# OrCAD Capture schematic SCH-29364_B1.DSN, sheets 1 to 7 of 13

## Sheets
1 A-02 PWR TREE: title: MCIMX6ULL-CM; rev: B1; company: Freescale Semiconductor; note: SCH-29364 PDF: SPF-29364; note: 6501 William Cannon Drive West; note: Austin, TX 78735-8598
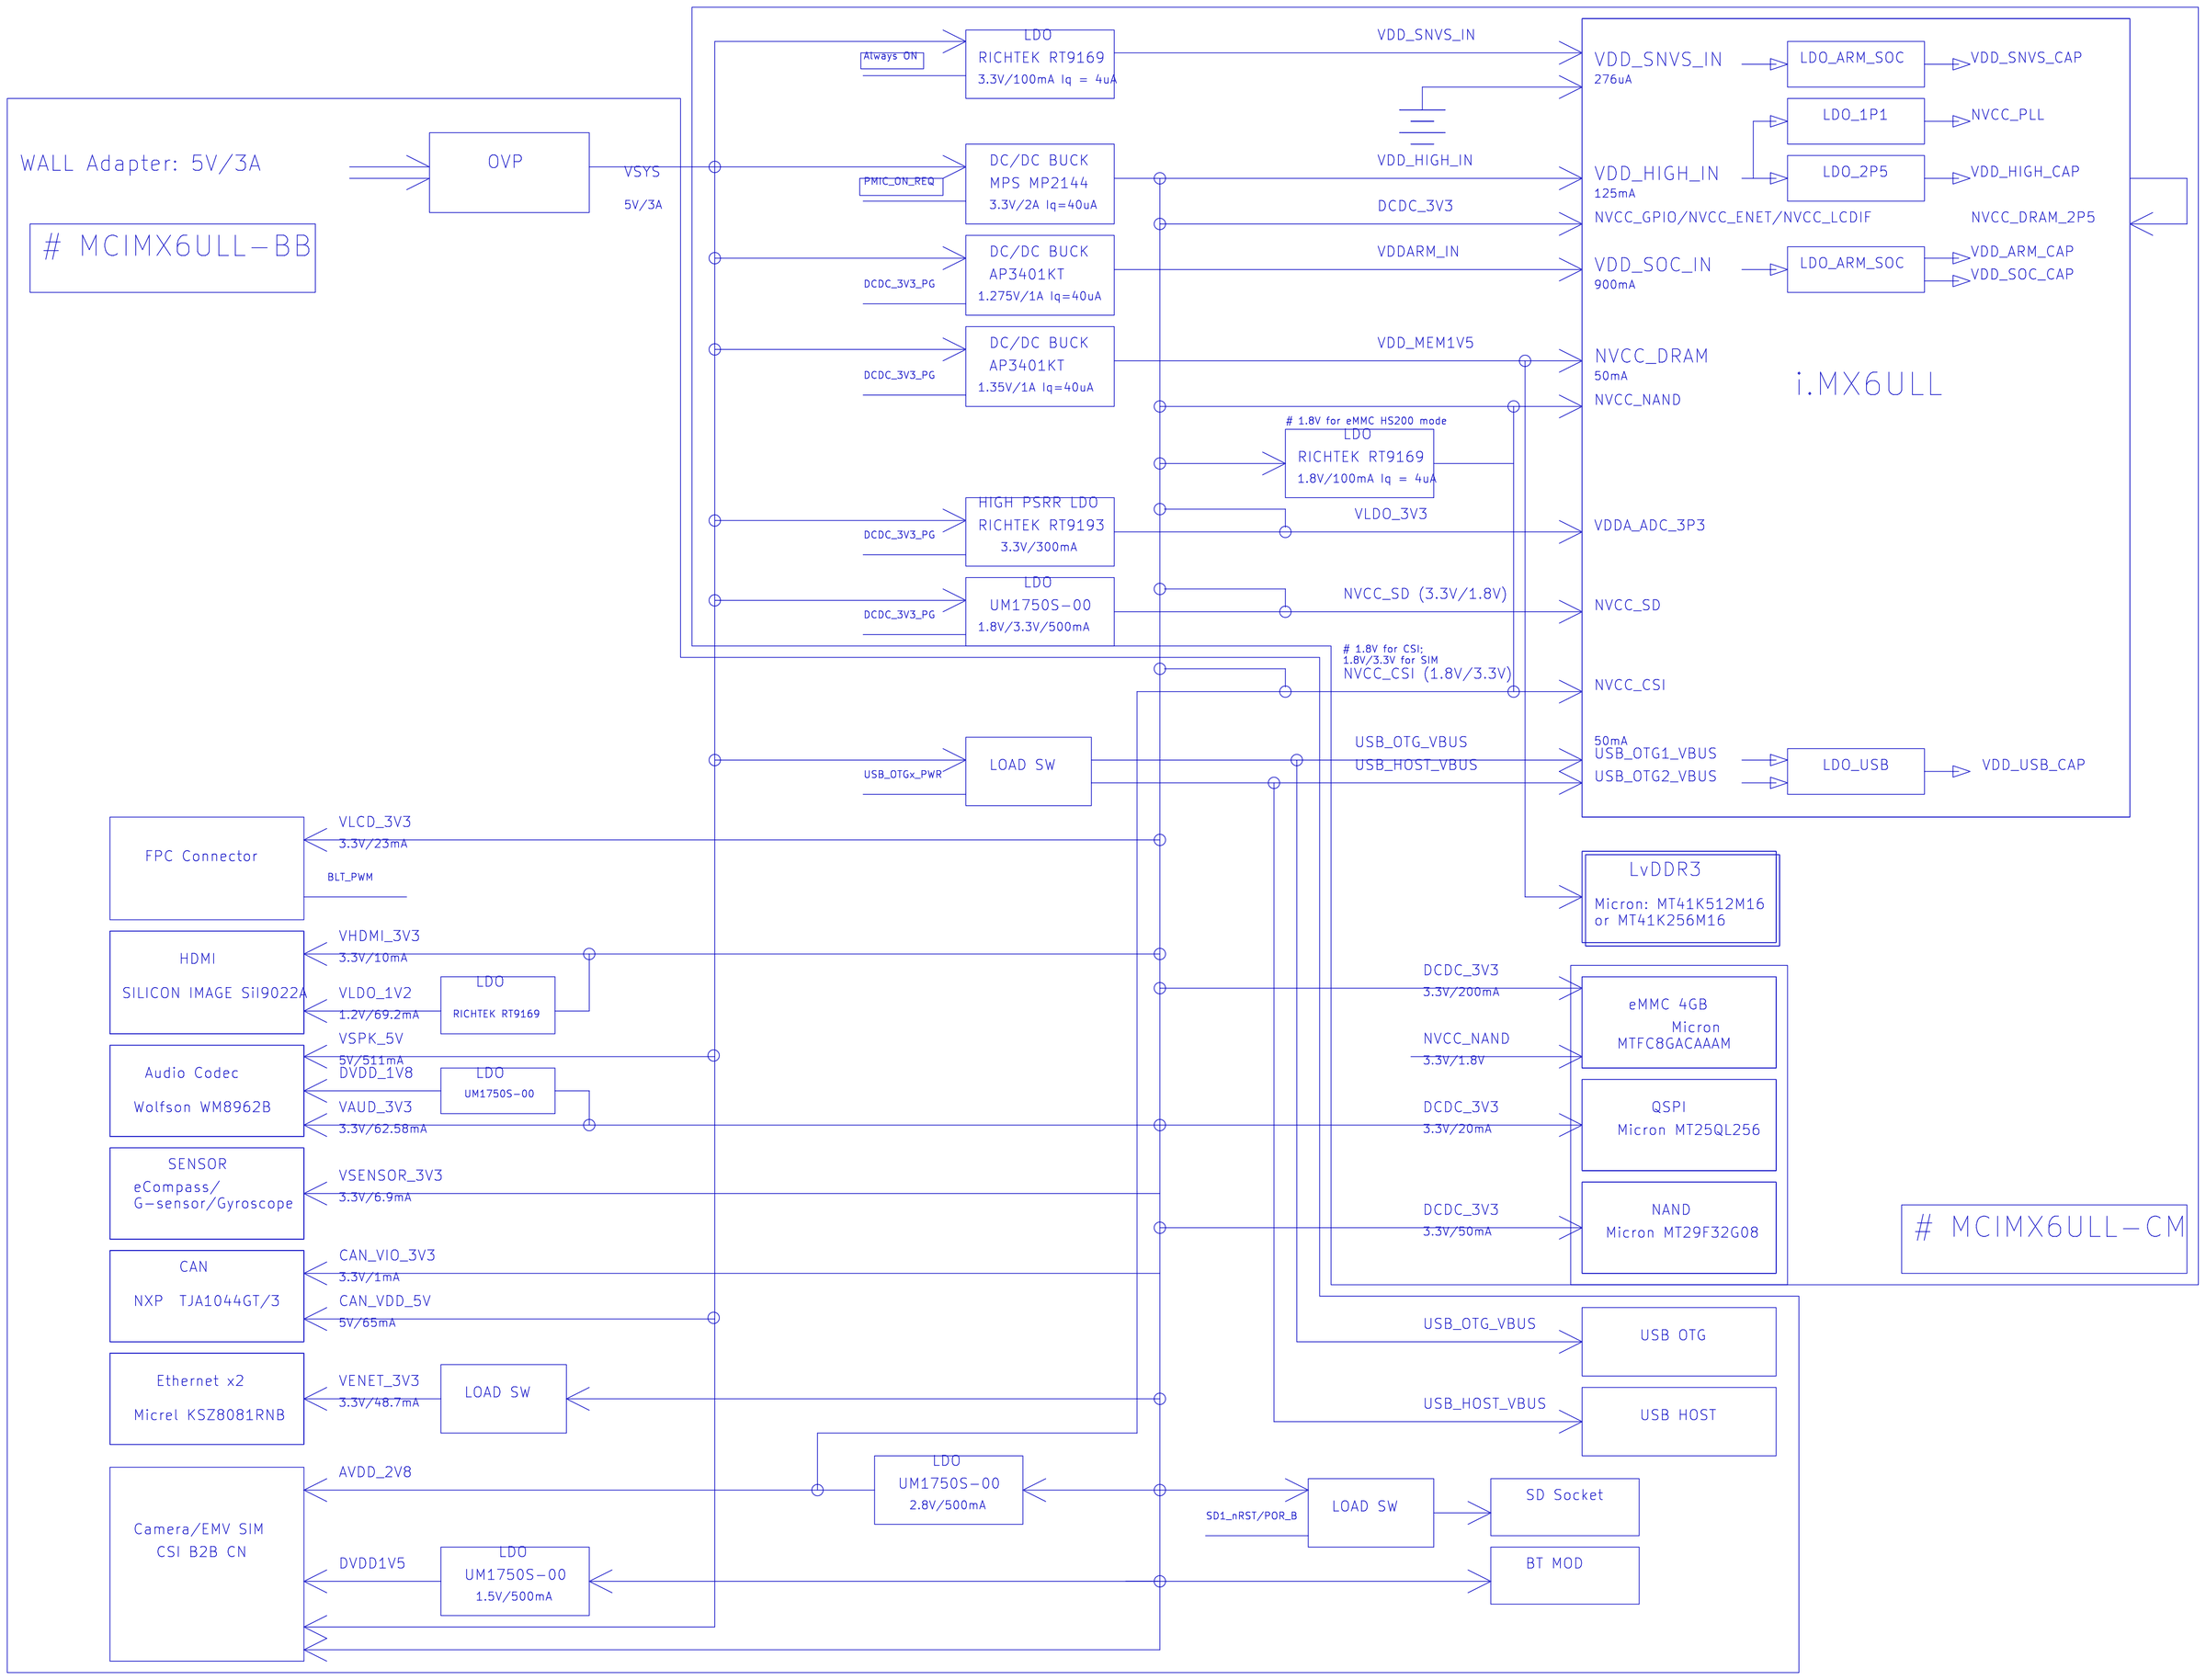
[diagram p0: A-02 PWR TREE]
2 A-01 BLOCK DIAGRAM
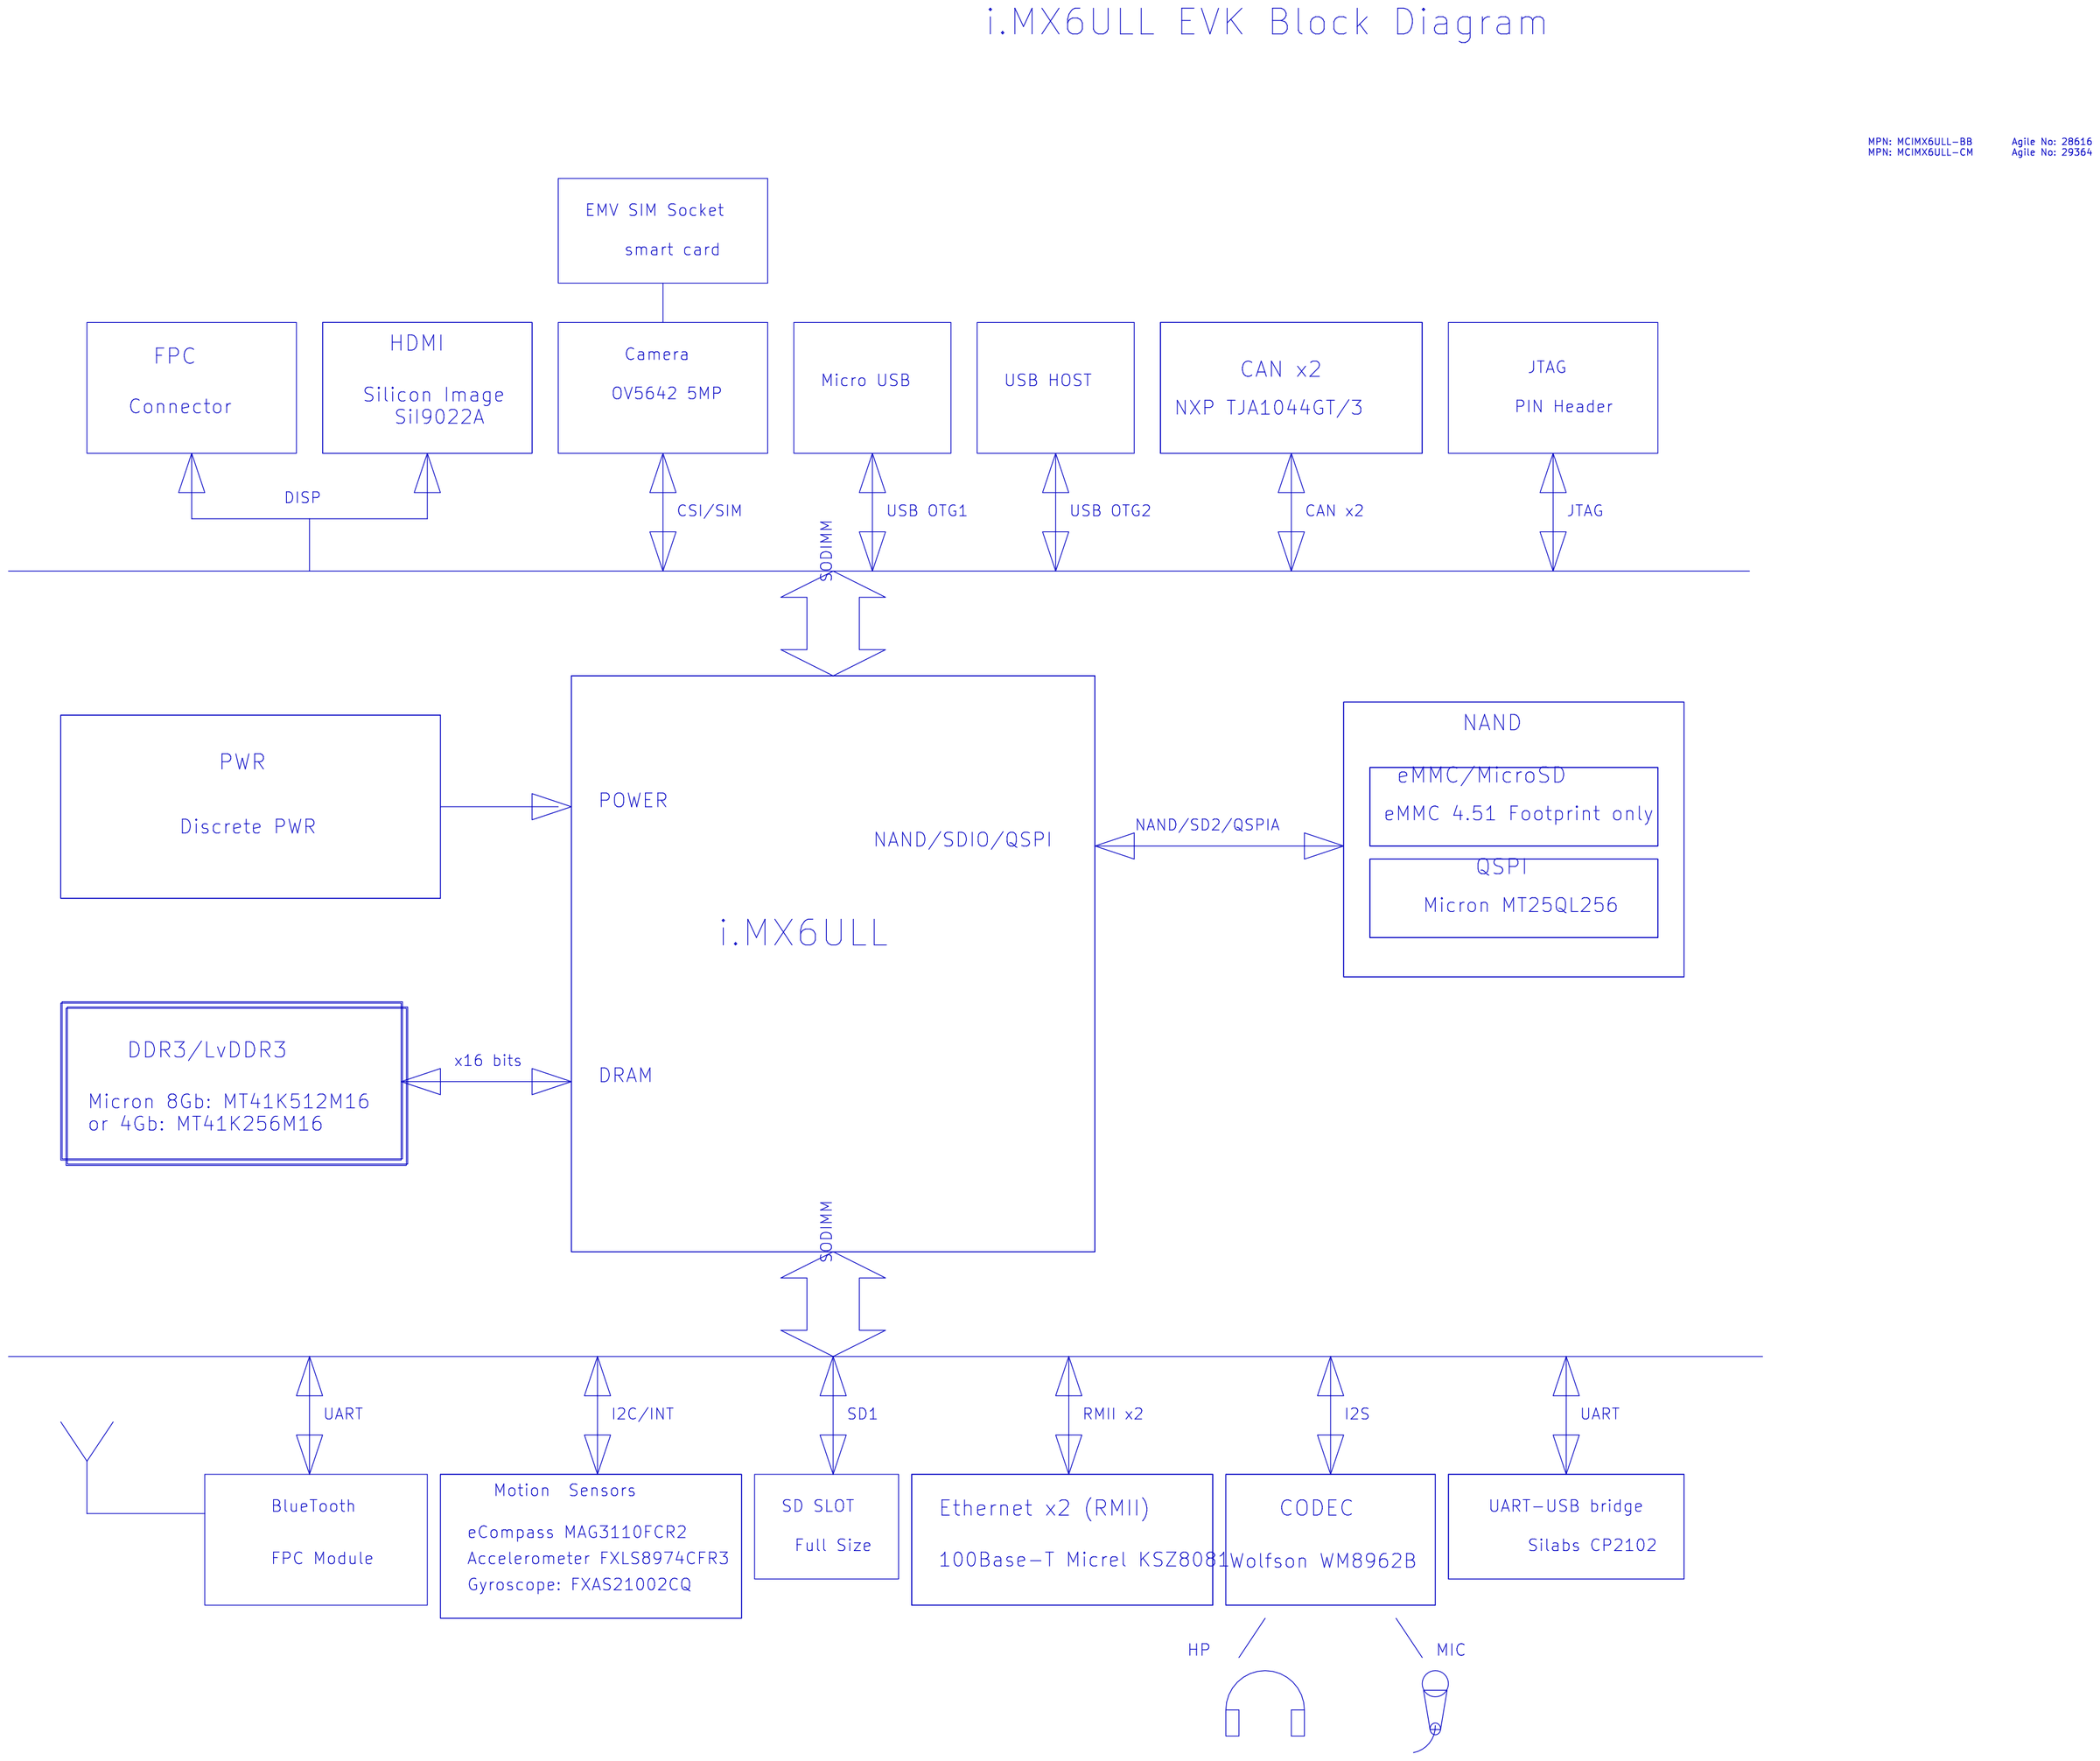
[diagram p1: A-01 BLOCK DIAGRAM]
3 A-00 COVER
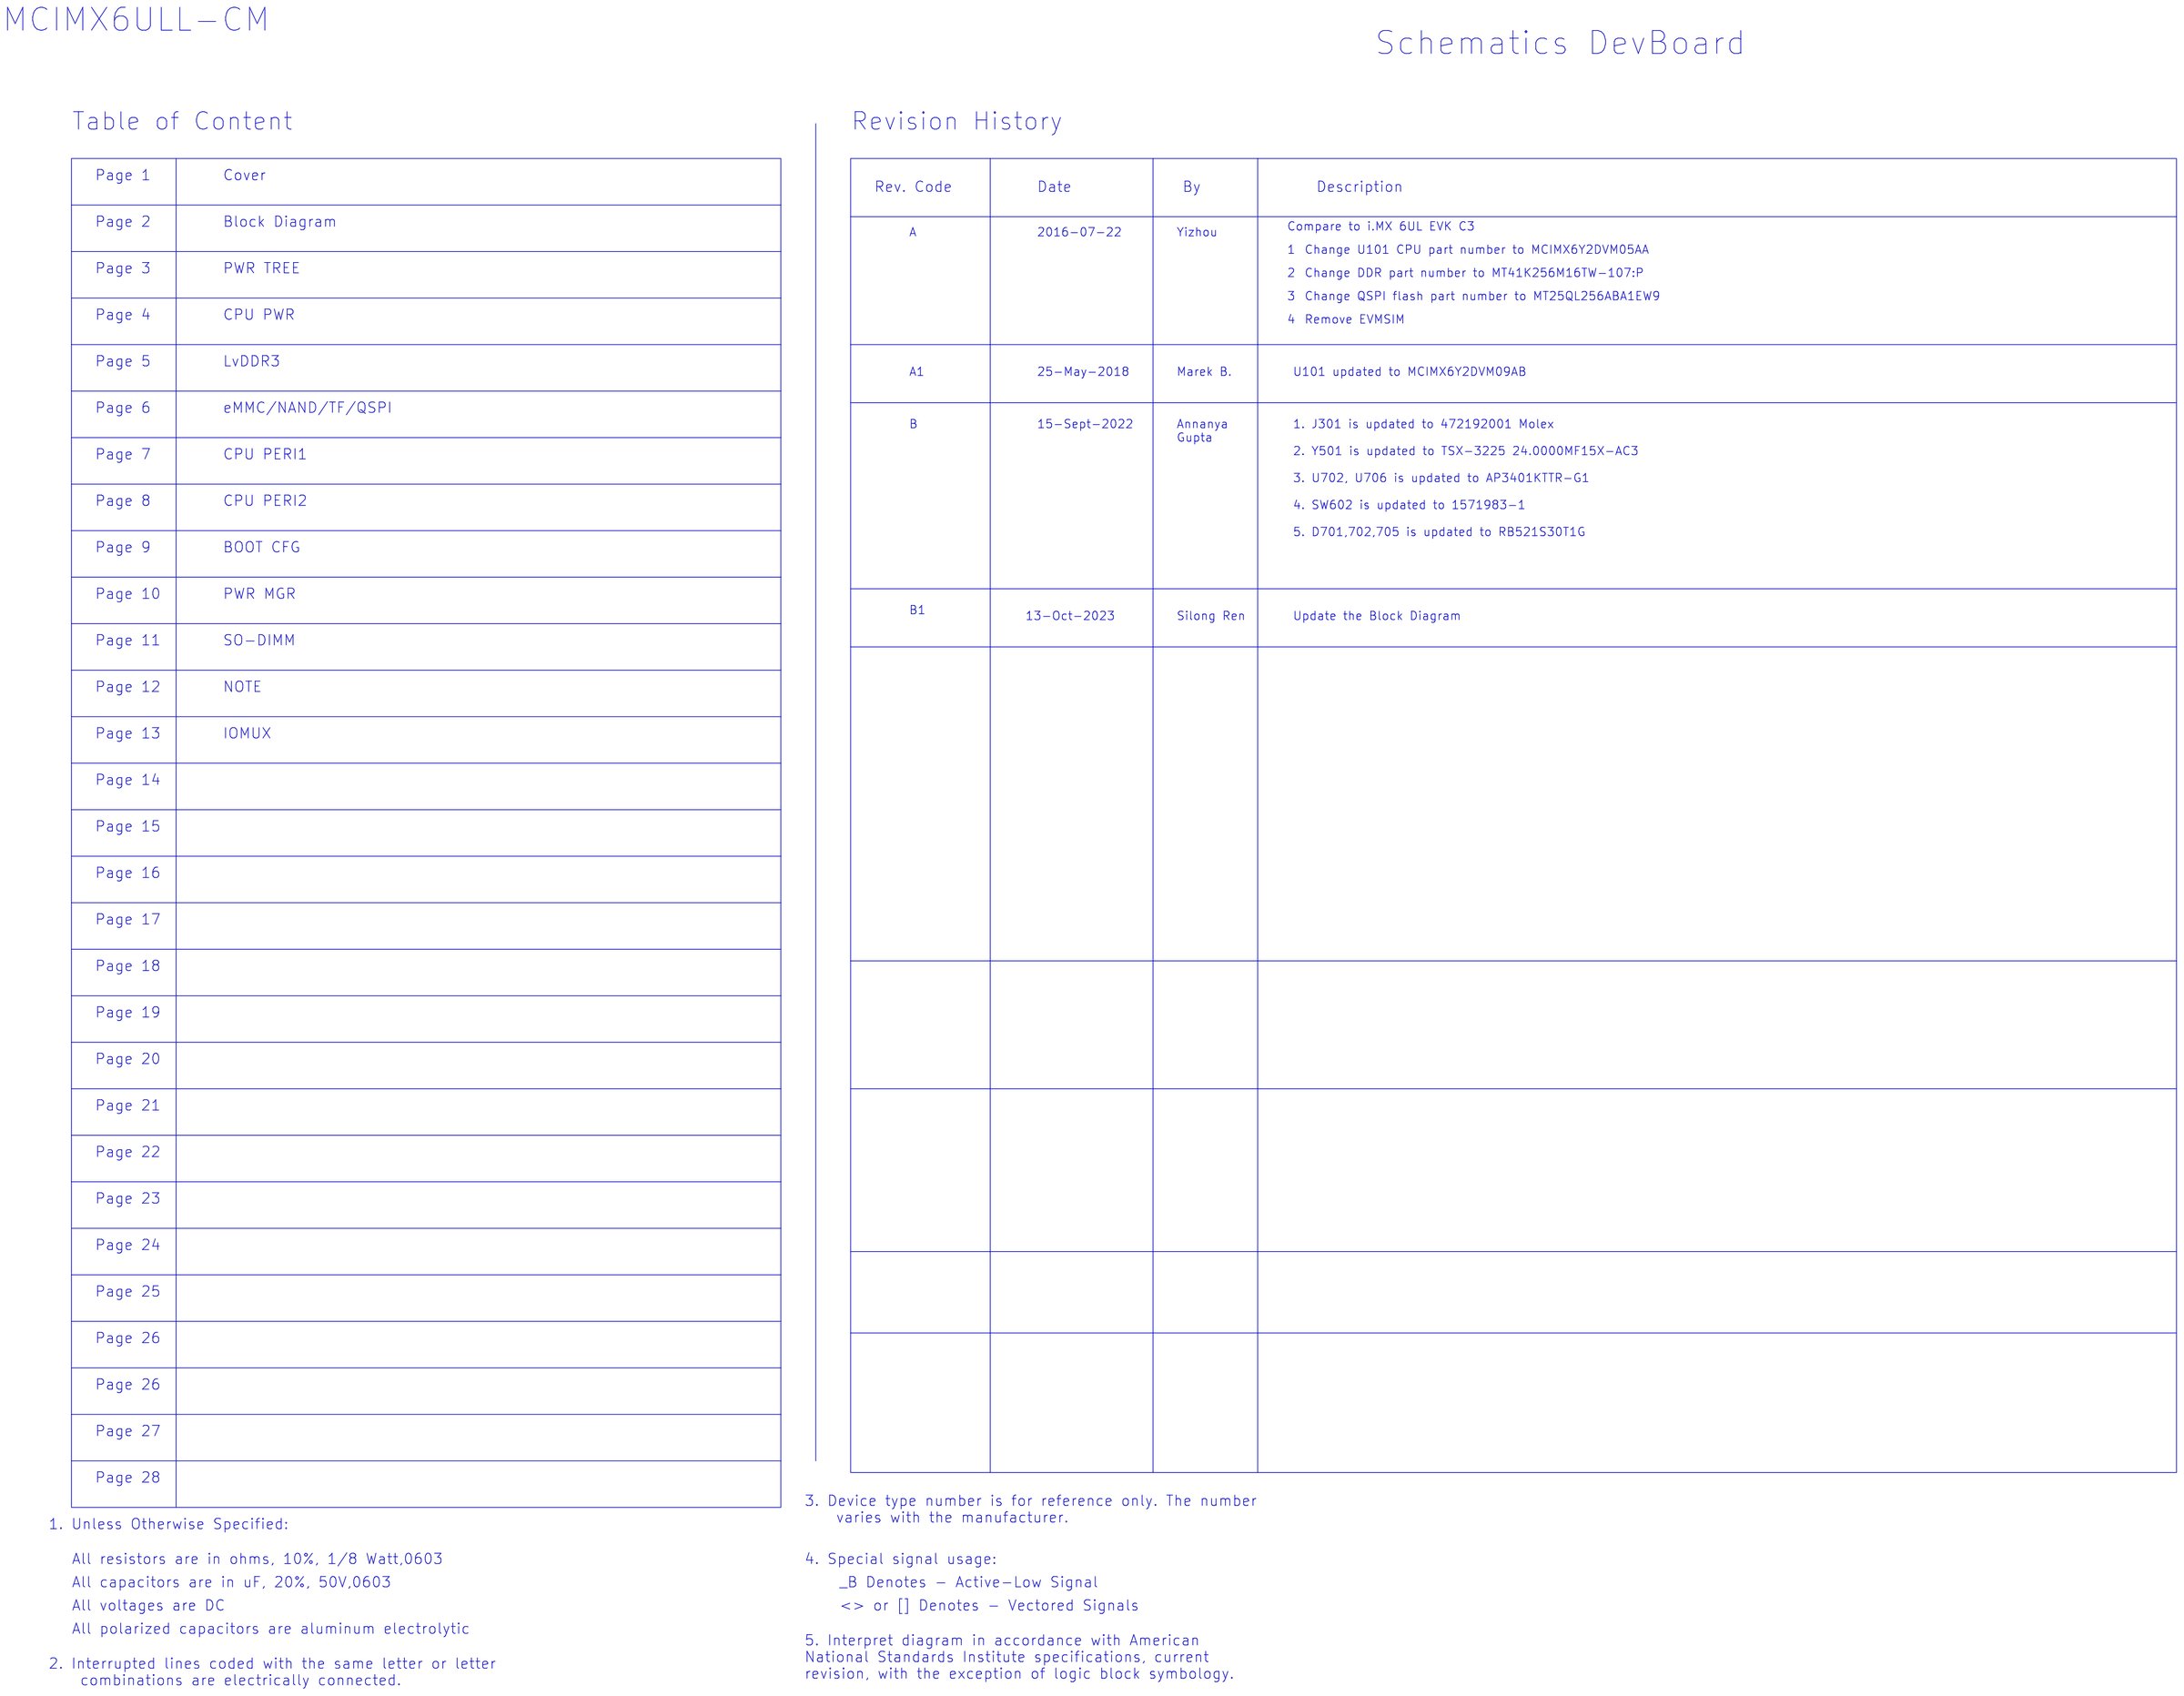
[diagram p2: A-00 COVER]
4 C-01 CPU PWR: size C
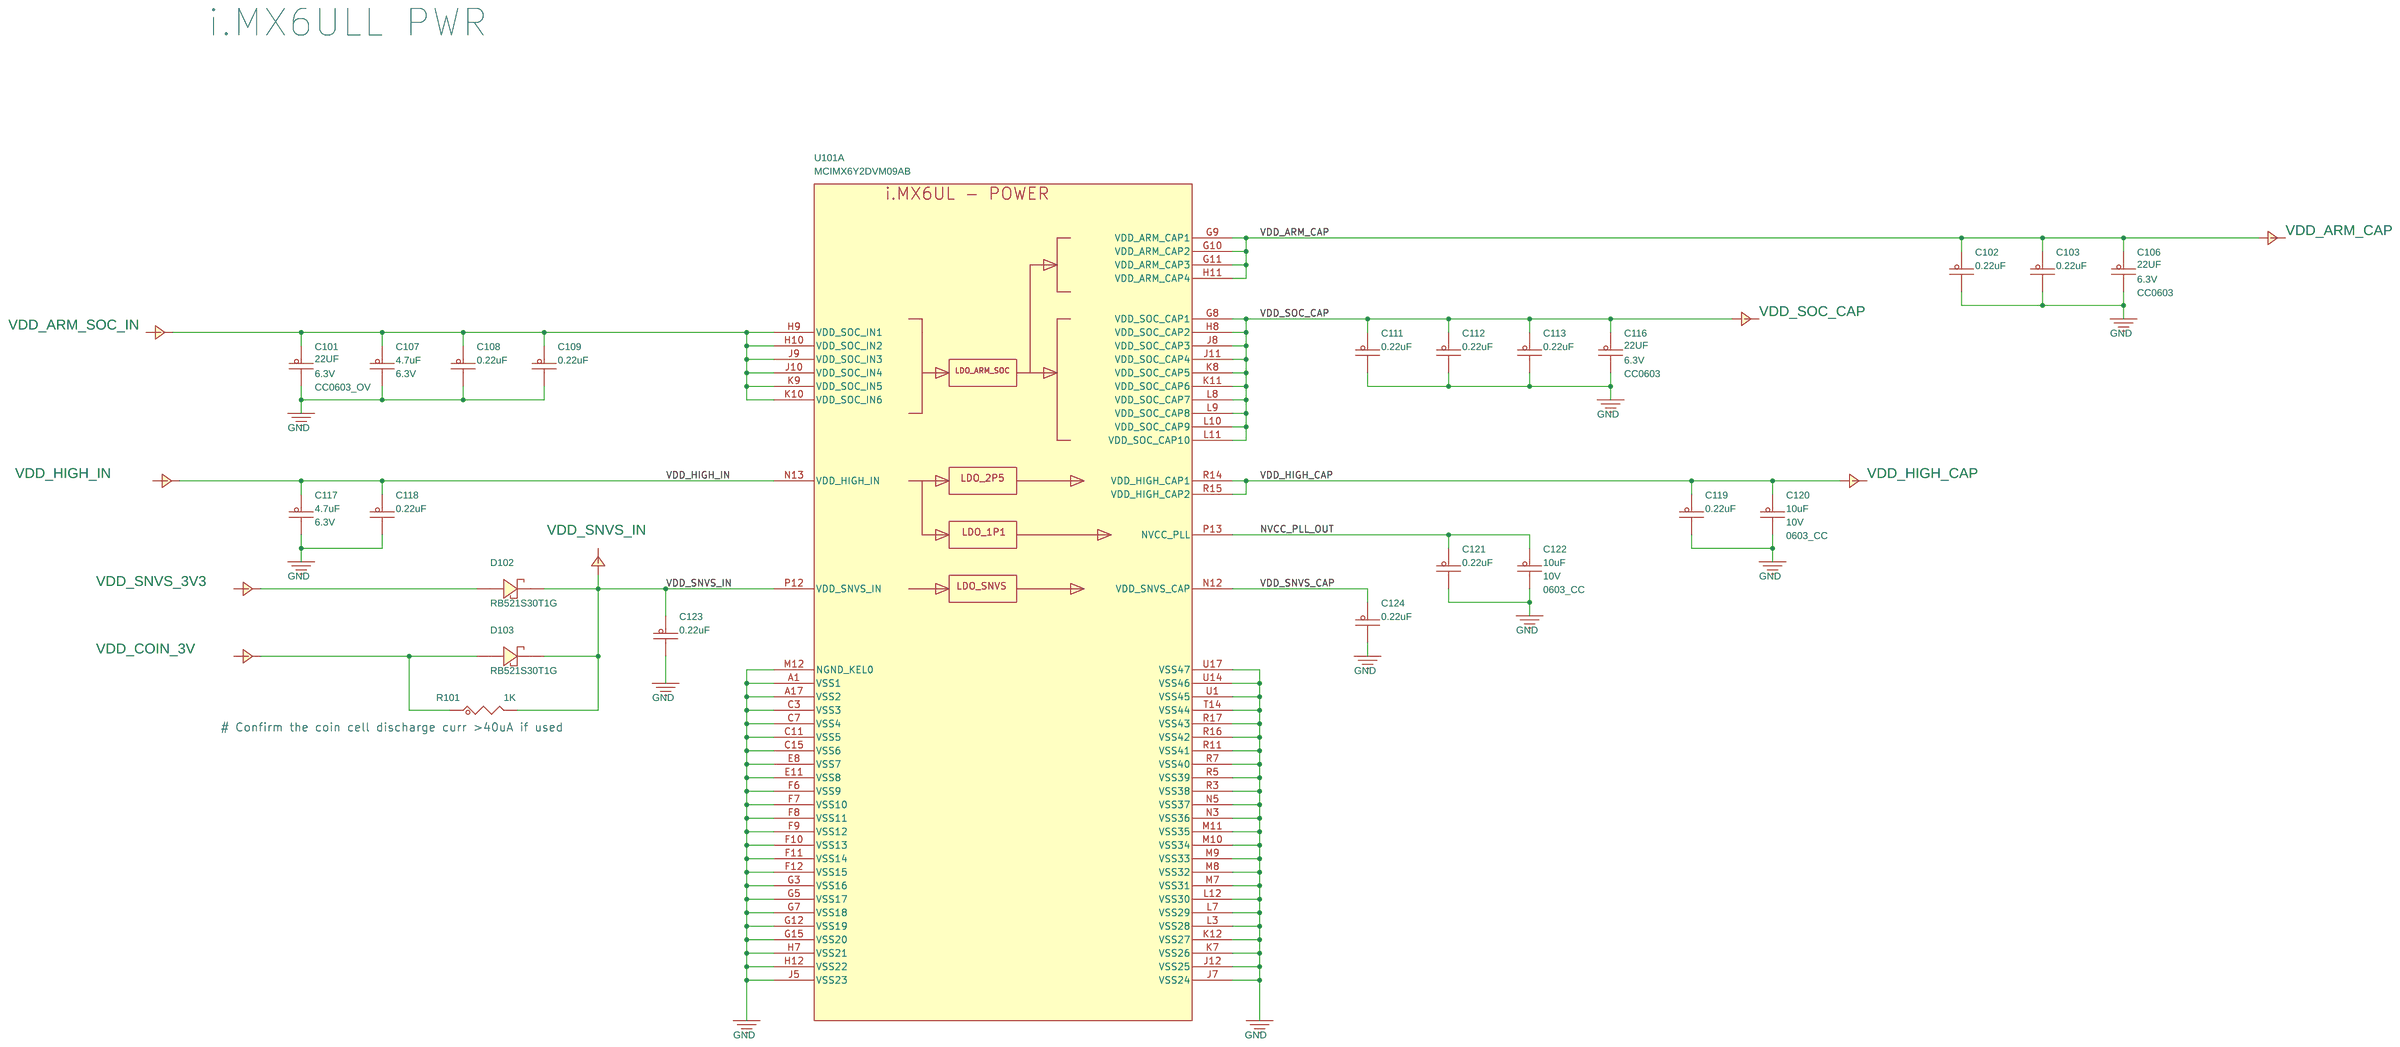
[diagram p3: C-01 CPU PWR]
5 C-02 LvDDR3: size C
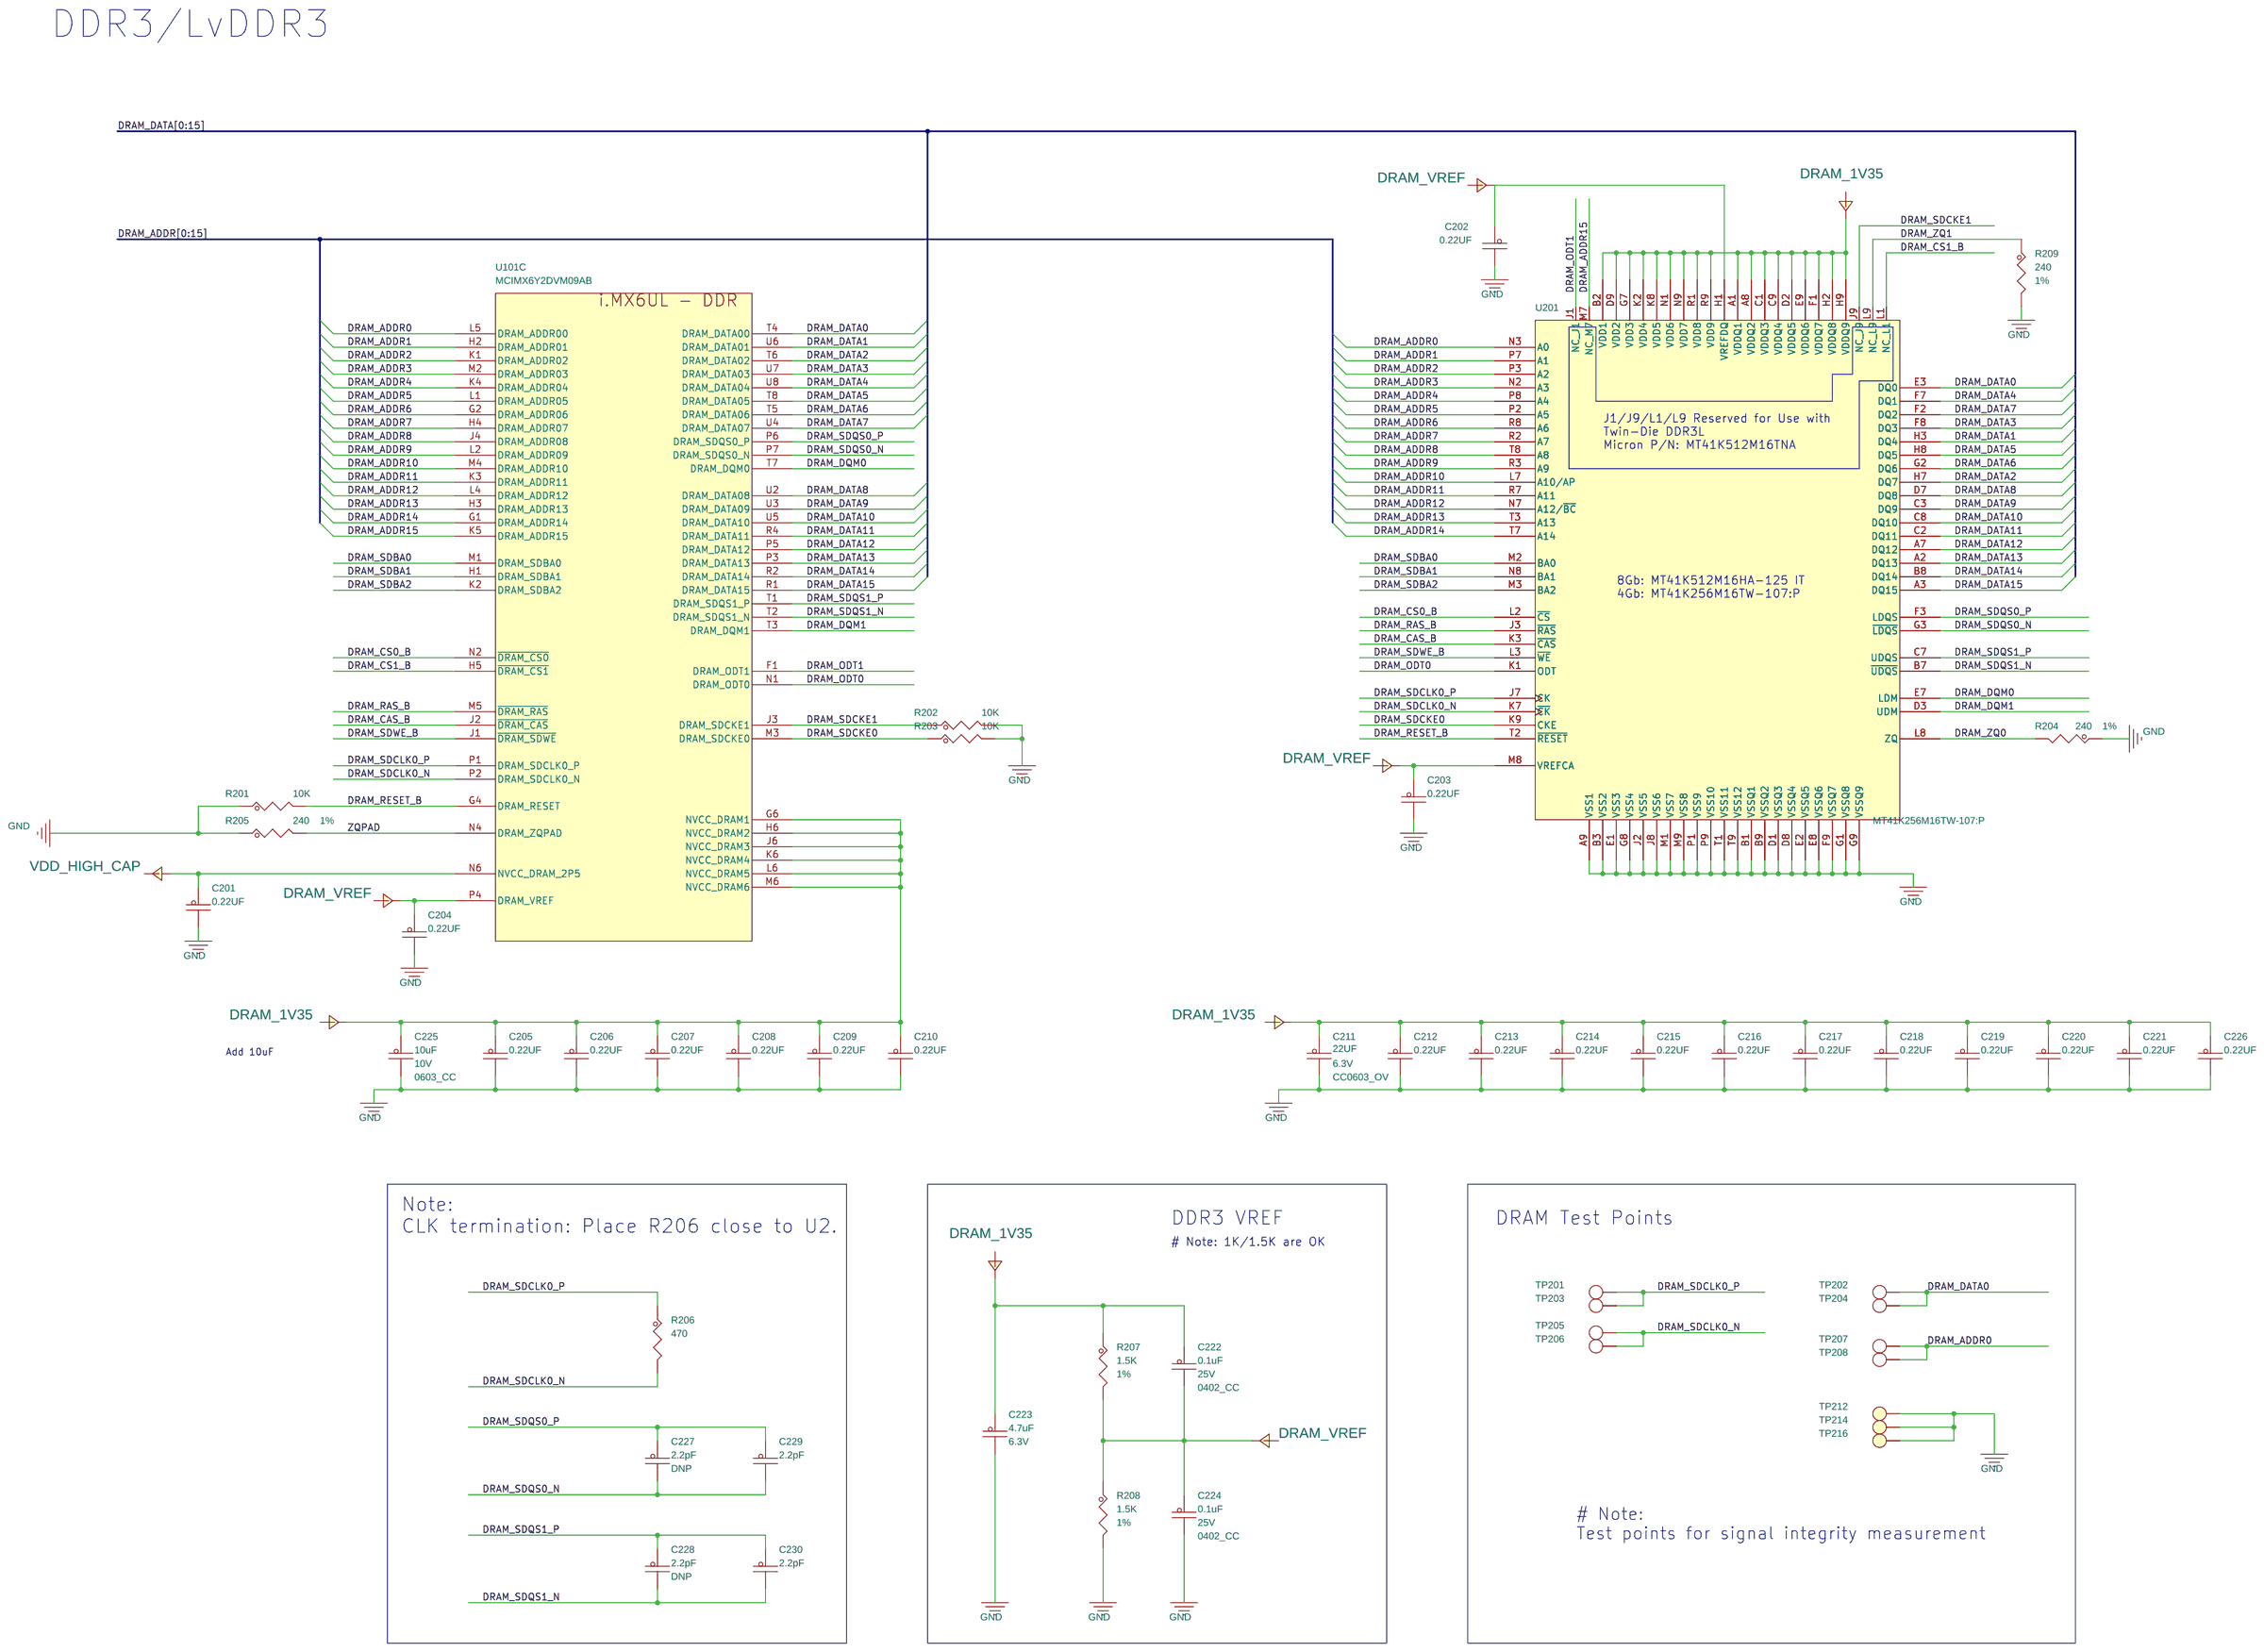
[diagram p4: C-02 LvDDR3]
6 C-04 CPU PERI1: size C
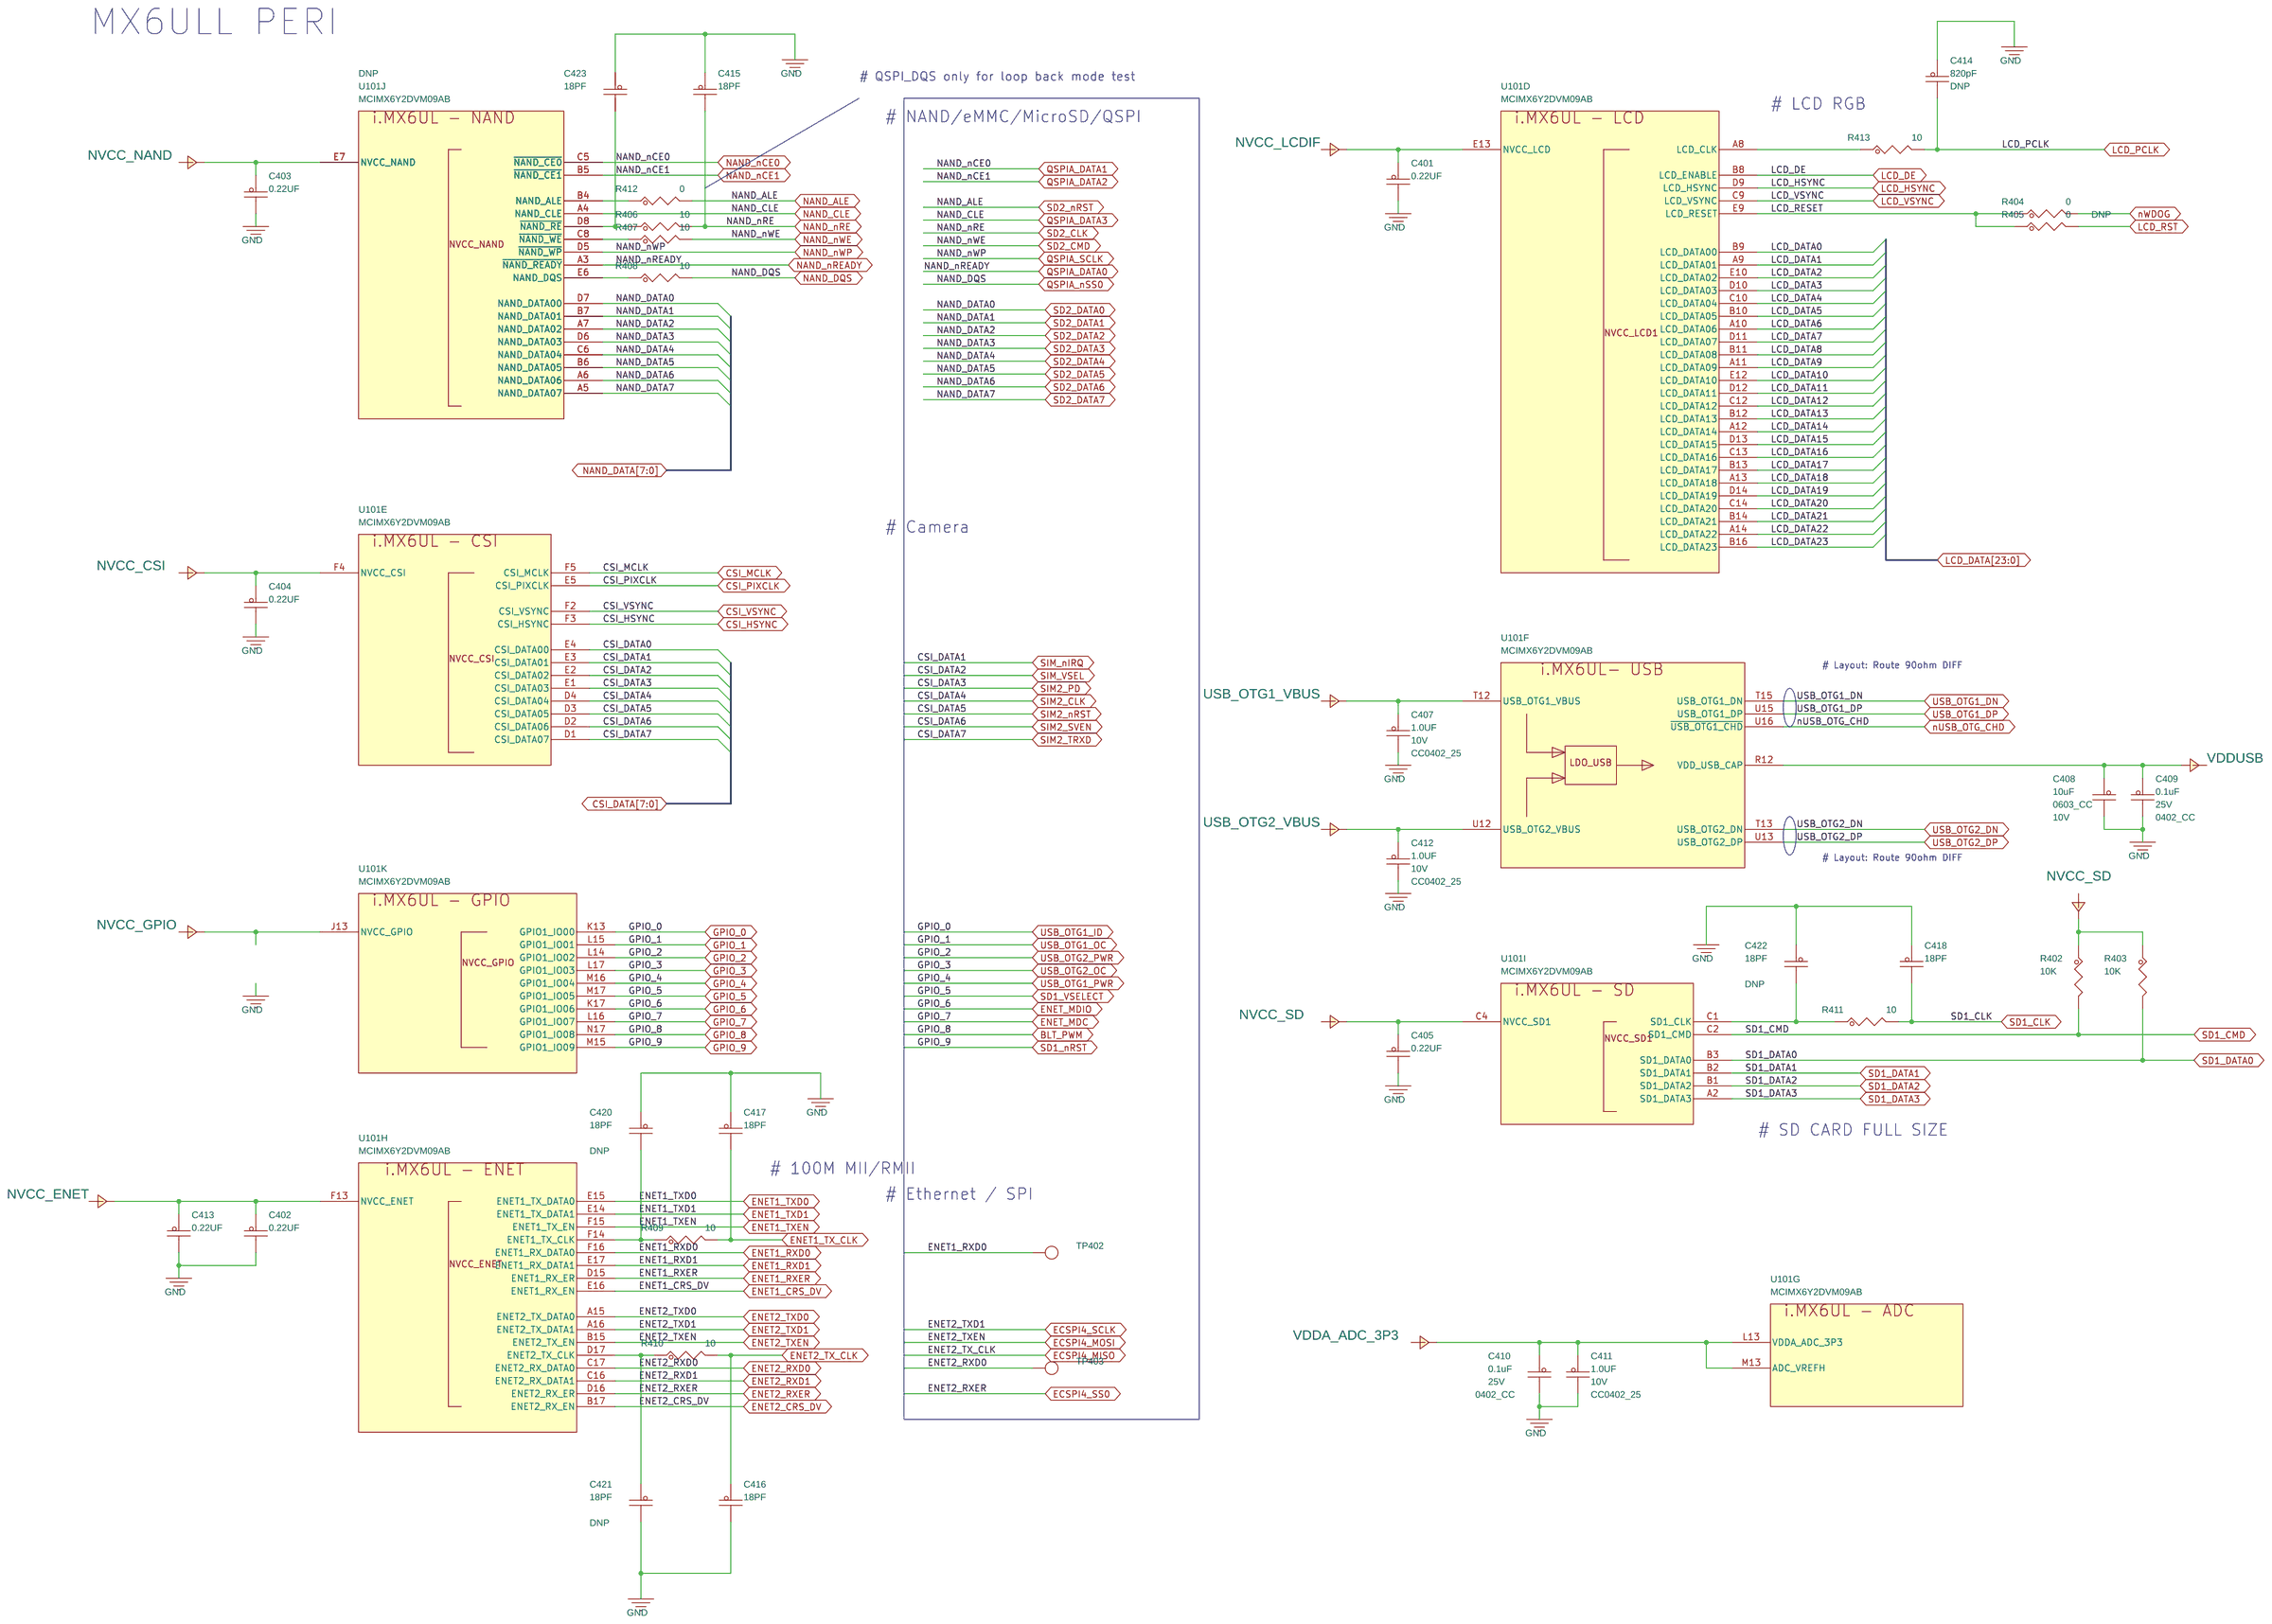
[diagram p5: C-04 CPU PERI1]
7 C-05 CPU PERI2: size C
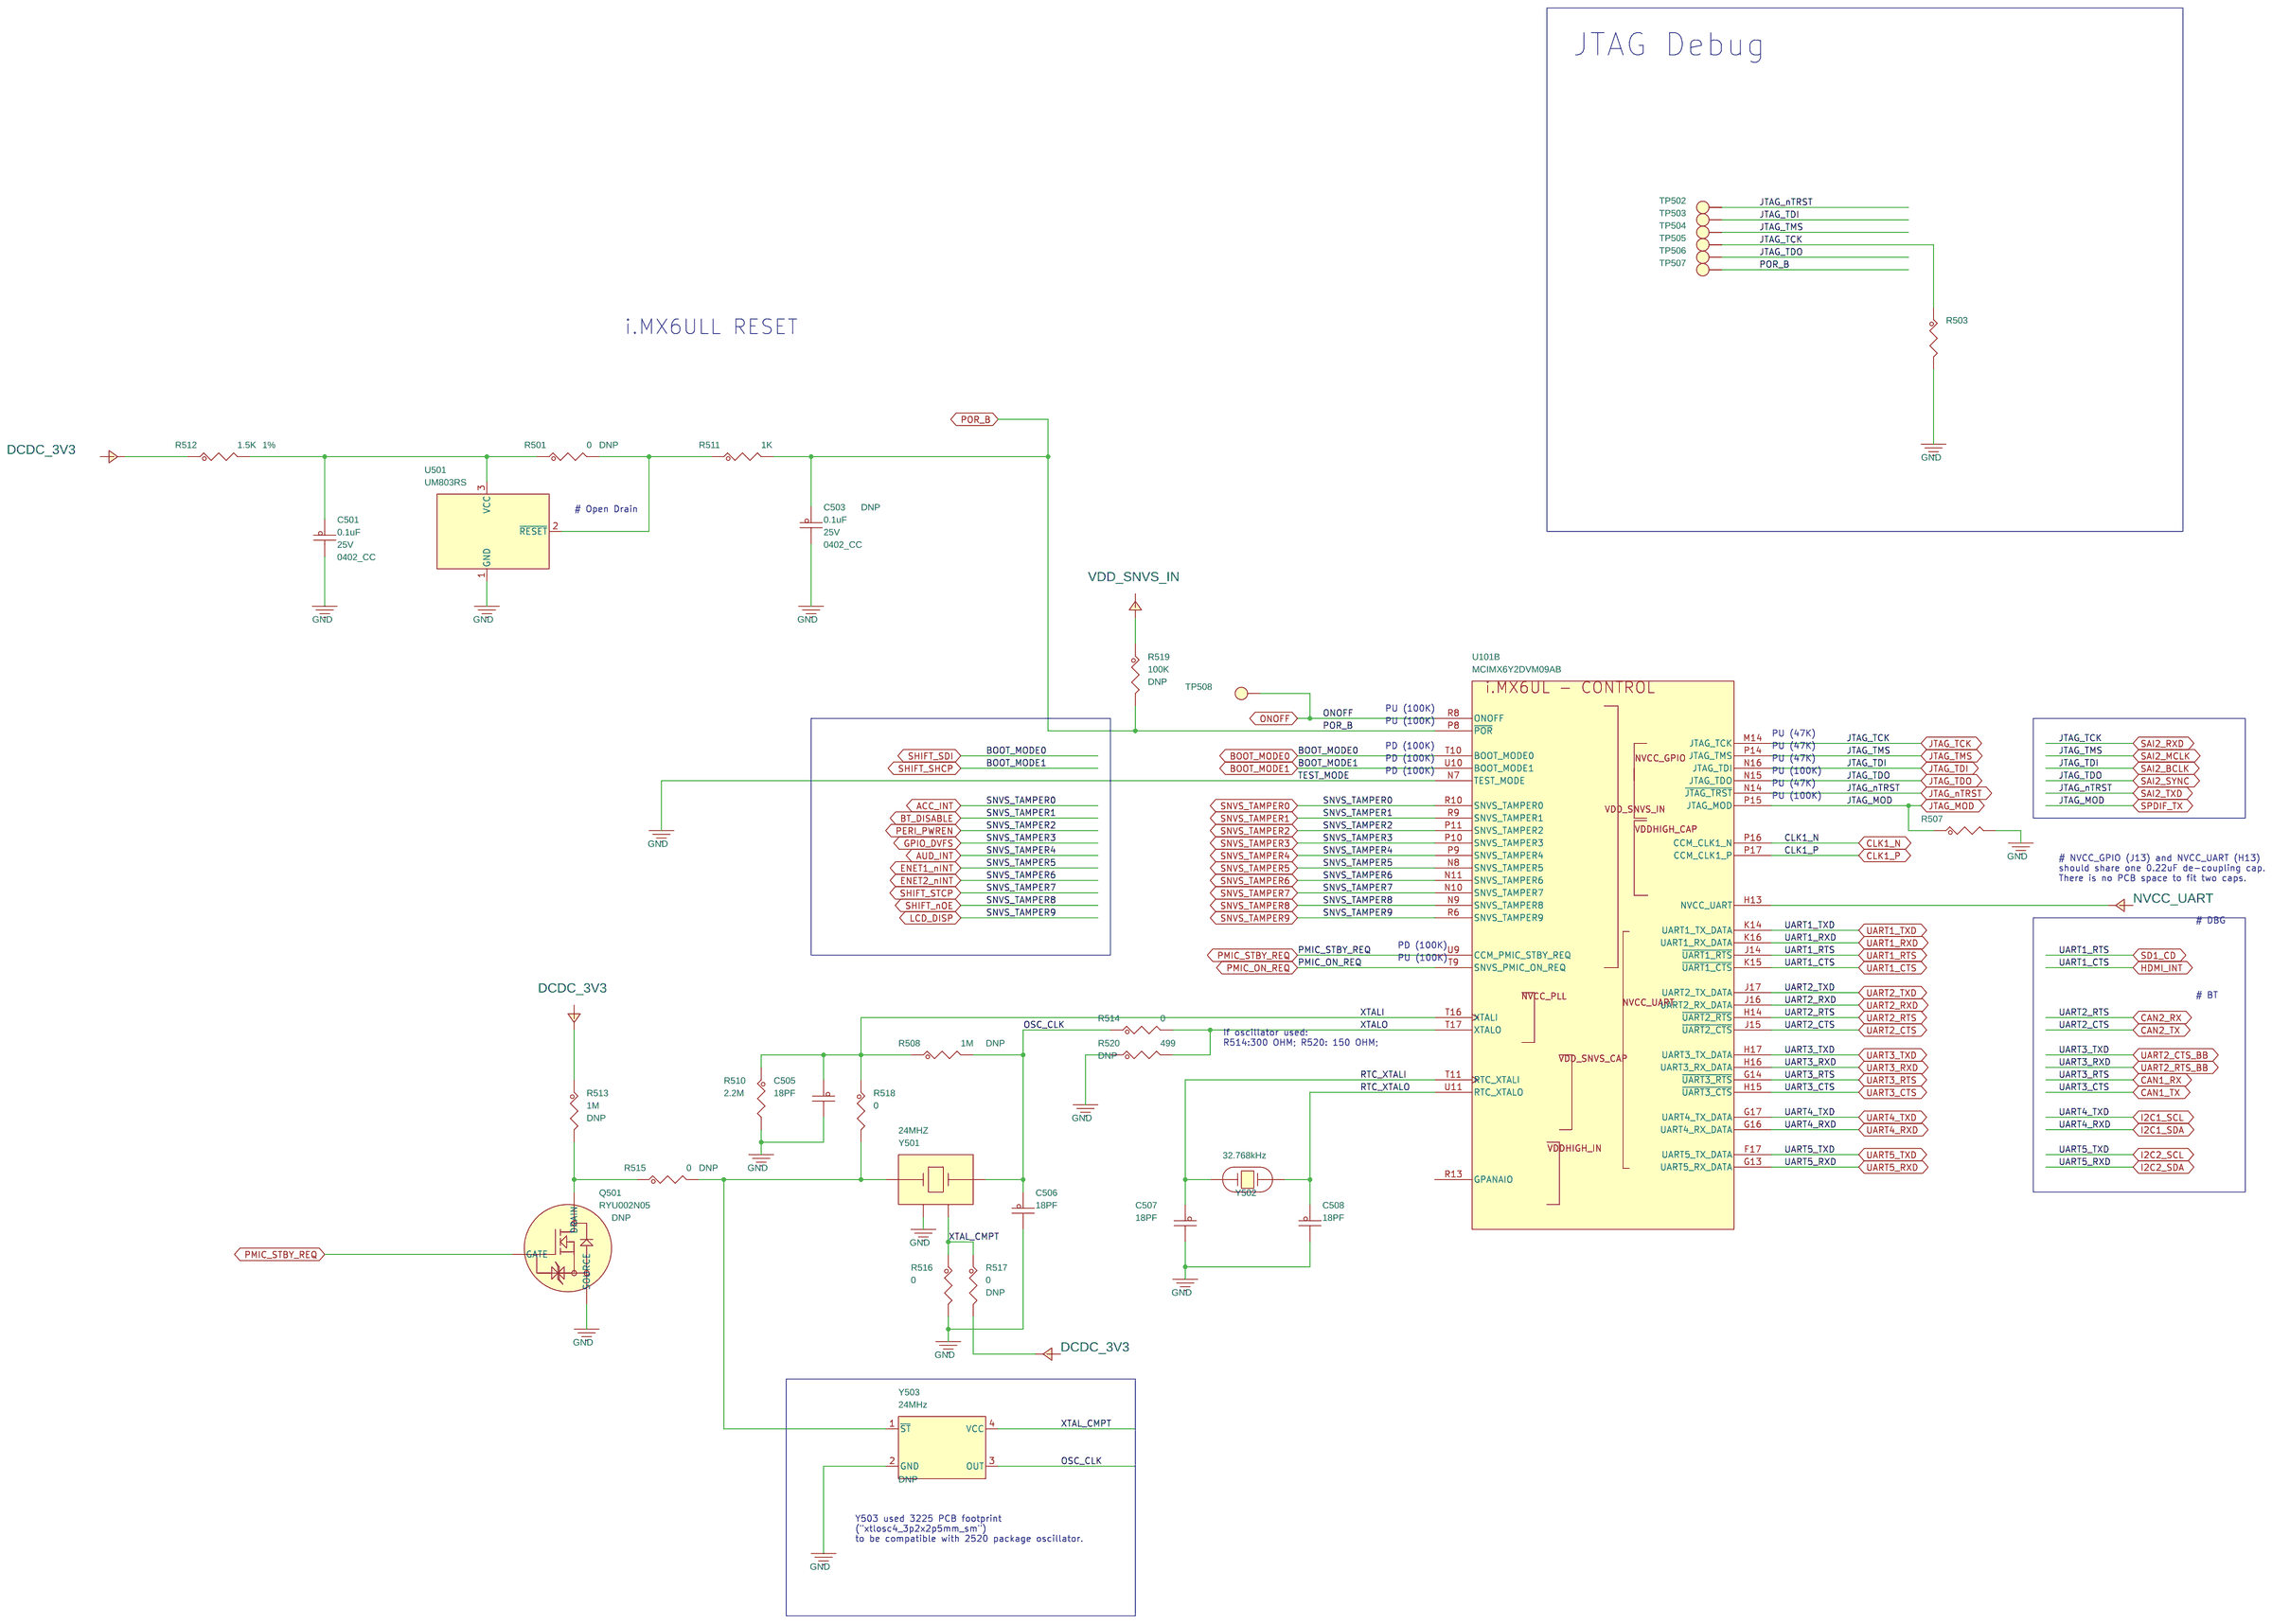
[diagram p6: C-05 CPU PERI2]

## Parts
sheet C-01 CPU PWR
C101  22UF  [CC0603_OV]
C102  0.22uF  [0402_CC]
C103  0.22uF  [0402_CC]
C106  22UF  [CC0603]
C107  4.7uF  [cc0402_tol0p15]
C108  0.22uF  [0402_CC]
C109  0.22uF  [0402_CC]
C111  0.22uF  [0402_CC]
C112  0.22uF  [0402_CC]
C113  0.22uF  [0402_CC]
C116  22UF  [CC0603]
C117  4.7uF  [cc0402_tol0p15]
C118  0.22uF  [0402_CC]
C119  0.22uF  [0402_CC]
C120  10uF  [0603_CC]
C121  0.22uF  [0402_CC]
C122  10uF  [0603_CC]
C123  0.22uF  [0402_CC]
C124  0.22uF  [0402_CC]
D102  RB521S30T1G  [sod_523]
D103  RB521S30T1G  [sod_523]
R101  1K  [0402_CC]
U101  MCIMX6Y2DVM09AB  [BGA289_0P8_14X14]  (sections A,B,C,D,E,F,G,H,I,J,K)
sheet C-02 LvDDR3
C201  0.22UF  [0402_CC]
C202  0.22UF  [0402_CC]
C203  0.22UF  [0402_CC]
C204  0.22UF  [0402_CC]
C205  0.22UF  [0402_CC]
C206  0.22UF  [0402_CC]
C207  0.22UF  [0402_CC]
C208  0.22UF  [0402_CC]
C209  0.22UF  [0402_CC]
C210  0.22UF  [0402_CC]
C211  22UF  [CC0603_OV]
C212  0.22UF  [0402_CC]
C213  0.22UF  [0402_CC]
C214  0.22UF  [0402_CC]
C215  0.22UF  [0402_CC]
C216  0.22UF  [0402_CC]
C217  0.22UF  [0402_CC]
C218  0.22UF  [0402_CC]
C219  0.22UF  [0402_CC]
C220  0.22UF  [0402_CC]
C221  0.22UF  [0402_CC]
C222  0.1uF  [0402_CC]
C223  4.7uF  [cc0402_tol0p15]
C224  0.1uF  [0402_CC]
C225  10uF  [0603_CC]
C226  0.22UF  [0402_CC]
C227  2.2pF  [0402_CC]
C228  2.2pF  [0402_CC]
C229  2.2pF  [0402_CC]
C230  2.2pF  [0402_CC]
R201  10K  [0402_CC]
R202  10K  [0402_CC]
R203  10K  [0402_CC]
R204  240  [0402_CC]
R205  240  [0402_CC]
R206  470  [0402_CC]
R207  1.5K  [0402_CC]
R208  1.5K  [0402_CC]
R209  240  [0402_CC]
TP201  TPAD_015  [TPAD_015]
TP202  TPAD_015  [TPAD_015]
TP203  TPAD_015  [TPAD_015]
TP204  TPAD_015  [TPAD_015]
TP205  TPAD_015  [TPAD_015]
TP206  TPAD_015  [TPAD_015]
TP207  TPAD_015  [TPAD_015]
TP208  TPAD_015  [TPAD_015]
TP212  TP_35MIL  [testpoint_35mil]
TP214  TP_35MIL  [testpoint_35mil]
TP216  TP_35MIL  [testpoint_35mil]
U201  MT41K256M16TW-107:P  [bga96_0p8_8p15x14p15]
sheet C-04 CPU PERI1
C401  0.22UF  [0402_CC]
C402  0.22UF  [0402_CC]
C403  0.22UF  [0402_CC]
C404  0.22UF  [0402_CC]
C405  0.22UF  [0402_CC]
C407  1.0UF  [CC0402_25]
C408  10uF  [0603_CC]
C409  0.1uF  [0402_CC]
C410  0.1uF  [0402_CC]
C411  1.0UF  [CC0402_25]
C412  1.0UF  [CC0402_25]
C413  0.22UF  [0402_CC]
C414  820pF  [0402_CC]
C415  18PF  [0402_CC]
C416  18PF  [0402_CC]
C417  18PF  [0402_CC]
C418  18PF  [0402_CC]
C420  18PF  [0402_CC]
C421  18PF  [0402_CC]
C422  18PF  [0402_CC]
C423  18PF  [0402_CC]
R402  10K  [0402_CC]
R403  10K  [0402_CC]
R404  0  [0402_CC]
R405  0  [0402_CC]
R406  10  [0402_CC]
R407  10  [0402_CC]
R408  10  [0402_CC]
R409  10  [0402_CC]
R410  10  [0402_CC]
R411  10  [0402_CC]
R412  0  [0402_CC]
R413  10  [0402_CC]
TP402  TPAD_015  [TPAD_015]
TP403  TPAD_015  [TPAD_015]
sheet C-05 CPU PERI2
C501  0.1uF  [0402_CC]
C503  0.1uF  [0402_CC]
C505  18PF  [0402_CC]
C506  18PF  [0402_CC]
C507  18PF  [0402_CC]
C508  18PF  [0402_CC]
Q501  RYU002N05  [SOT323_3]
R501  0  [0402_CC]
R503  10K  [0402_CC]
R507  10K  [0402_CC]
R508  1M  [0402_CC]
R510  2.2M  [0402_CC]
R511  1K  [0402_CC]
R512  1.5K  [0402_CC]
R513  1M  [0402_CC]
R514  0  [0402_CC]
R515  0  [0402_CC]
R516  0  [0402_CC]
R517  0  [0402_CC]
R518  0  [0402_CC]
R519  100K  [0402_CC]
R520  499  [0402_CC]
TP502  TP_35MIL  [testpoint_35mil]
TP503  TP_35MIL  [testpoint_35mil]
TP504  TP_35MIL  [testpoint_35mil]
TP505  TP_35MIL  [testpoint_35mil]
TP506  TP_35MIL  [testpoint_35mil]
TP507  TP_35MIL  [testpoint_35mil]
TP508  TP_35MIL  [testpoint_35mil]
U501  UM803RS  [sot-23]
Y501  24MHZ  [xtlosc4_3p2x2p5mm_sm]
Y502  32.768kHz  [XTAL2-3p2x1p5-SM]
Y503  24MHz  [xtlosc4_2p6x2p1mm_sm]

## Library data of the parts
C101 C211 = CAP_NP: CAP CER 22UF 6.3V 20% X5R 0603; AGILE_PN: 150-78467; CAD_APPROVED: Yes; FPLIST: CC0603_OV,CC0603,0603_CC; HEIGHT: 1MM; MFG_NAME01: SAMSUNG; MFG_PN01: CL10A226MQ8NRNE; Package Size: 0603; ROHS: Yes; Rated Voltage: 6.3V; Temp Range: -55C to +85C; Tolerance: 20%; VOLTAGE: 6.3V; voltage rating: 6.3V
C102 C103 C108 C109 C111-C113 C118 C119 C121 C123 C124 = CAP_NP: CAP CER 0.22UF 6.3V 20% X5R 0402; AGILE_PN: 150-76271; CAD_APPROVED: Yes; FPLIST: CC0402_25,CC0402_HD,0402_CC; HEIGHT: 0.55MM; MFG_NAME01: KEMET; MFG_PN01: C0402C224M9PAC; Package Size: 0402; Package Type: Tape&reel; ROHS: Yes; Rated Voltage: 6.3V; Temp Range: -55C to +85C; Tolerance: 20%; VOLTAGE: 6.3V
C106 C116 = CAP_NP: CAP CER 22UF 6.3V 20% X5R 0603; AGILE_PN: 150-78467; CAD_APPROVED: Yes; FPLIST: CC0603_OV,CC0603,0603_CC_NSP; HEIGHT: 1MM; MFG_NAME01: SAMSUNG; MFG_PN01: CL10A226MQ8NRNE; Package Size: 0603; ROHS: Yes; Rated Voltage: 6.3V; Temp Range: -55C to +85C; Tolerance: 20%; VOLTAGE: 6.3V; voltage rating: 6.3V
C107 C117 C223 = CAP_NP: CAP CER 4.7UF 6.3V 20% X5R 0402; AGILE_PN: 150-78463; CAD_APPROVED: Yes; FPLIST: CC0402_25,CC0402_HD,0402_CC; HEIGHT: 0.65MM; MFG_NAME01: TDK; MFG_PN01: C1005X5R0J475M; ROHS: Yes; Rated Voltage: 6.3V; Temp Range: -55C to +85C; Tolerance: 20%; VOLTAGE: 6.3V; voltage rating: 6.3V
C120 C122 C225 C408 = CAP_NP: CAP CER 10UF 10V 20% X5R 0603; AGILE_PN: 150-78609; CAD_APPROVED: Yes; FPLIST: CC0603_OV,CC0603,0603_CC; HEIGHT: 1.016MM; MFG_NAME01: TDK; MFG_PN01: C1608X5R1A106M; Package Size: 0603; Package Type: Paper Tape; ROHS: Yes; Rated Voltage: 10V; Temp Range: -55C to +85C; Tolerance: 20%; VOLTAGE: 10V
D102 D103 = DIODE_SCHTKY: DIODE SCH 200MA 30V AEC-Q101 SOD-523; 3D_Mechanical_Footprint_File: http://fcl.am.freescale.net/ALLEGRO/step/sod_523.STEP; AGILE_PN: 480-78501; CAD_APPROVED: Yes; HEIGHT: 0.7MM; MFG_NAME01: ON SEMICONDUCTOR; ROHS: Yes; Rated Voltage: 30V
R101 R511 = RES: RES MF 1.0K 1/16W 5% 0402; AGILE_PN: 470-75555; CAD_APPROVED: Yes; FPLIST: RC0402_25,RC0402_HD,RC0402_X2,0402_CC; HEIGHT: 0.41mm; MFG_NAME01: BOURNS; MFG_PN01: CR0402-JW-102GLF; ROHS: Yes; Tolerance: 5%
U101 = MCIMX6Y2DVM05AA_PBGA_289P: IC CPU ARM COREA7 900MHZ 32BIT 3-3.6V PBGA289; AGILE_PN: 330-77080; CAD_APPROVED: Yes; HEIGHT: 1.32MM; MFG_NAME01: NXP SEMICONDUCTOR; ROHS: Yes; Temp Range: 0C to +95C; Temp_Range: 0C to +95C; VOLTAGE: 3-3.6V
C201-C210 C212-C221 C226 C401-C405 C413 = CAP_NP: CAP CER 0.22UF 10V 10% X5R 0402; AGILE_PN: 150-77358; CAD_APPROVED: Yes; FPLIST: CC0402_25,CC0402_HD,0402_CC; HEIGHT: 0.55MM; MFG_NAME01: NIC COMPONENTS CORP; MFG_PN01: NMC0402X5R224K10TRPF; ROHS: Yes; Rated Voltage: 10V; Temp Range: -55C to +85C; Tolerance: 10%; VOLTAGE: 10V
C222 C224 C409 C410 C501 = CAP_NP: CAP CER 0.1UF 25V 10% X5R 0402; AGILE_PN: 150-78633; CAD_APPROVED: Yes; FPLIST: CC0402_25,CC0402_HD,0402_CC; HEIGHT: 0.55MM; MFG_NAME01: YAGEO AMERICA; MFG_PN01: CC0402KRX5R8BB104; Package Size: 0402; ROHS: Yes; Rated Voltage: 25V; Temp Range: -55C to +85C; Tolerance: 10%; VOLTAGE: 25V
C227 C228 = CAP_NP: CAP CER 2.2pF 50V 0.25pF C0G 0402; AGILE_PN: 150-79743; ASSY_OPT: DNP; CAD_APPROVED: Yes; FPLIST: CC0402_25,CC0402_HD,0402_CC; HEIGHT: 0.56MM; MFG_NAME01: AVX; MFG_PN01: 04025A2R2CAT4A; ROHS: Yes; Rated Voltage: 50V; Temp Range: -55C to +125C; Tolerance: 11.36%; VOLTAGE: 50V
C229 C230 = CAP_NP: CAP CER 2.2pF 50V 0.25pF C0G 0402; AGILE_PN: 150-79743; CAD_APPROVED: Yes; FPLIST: CC0402_25,CC0402_HD,0402_CC; HEIGHT: 0.56MM; MFG_NAME01: AVX; MFG_PN01: 04025A2R2CAT4A; ROHS: Yes; Rated Voltage: 50V; Temp Range: -55C to +125C; Tolerance: 11.36%; VOLTAGE: 50V
R201-R203 R402 R403 = RES: RES MF 10K 1/16W 5% 0402; AGILE_PN: 470-75557; CAD_APPROVED: Yes; FPLIST: RC0402_25,RC0402_HD,0402_CC; HEIGHT: 0.4 MM; MFG_NAME01: BOURNS; MFG_PN01: CR0402-JW-103GLF; ROHS: Yes; Tolerance: 5%
R204 R205 R209 = RES: RES MF 240 OHM 1/16W 1% 0402; AGILE_PN: 470-30776; CAD_APPROVED: Yes; FPLIST: RC0402_25,RC0402_HD,0402_CC; HEIGHT: 0.40 MM; MFG_NAME01: WALSIN TECHNOLOGY CORP.; MFG_PN01: WR04X2400FTL; ROHS: Yes; Tolerance: 1%
R206 = RES: RES MF 470 OHM 1/16W 5% 0402; AGILE_PN: 470-30315; CAD_APPROVED: Yes; FPLIST: RC0402_25,RC0402_HD,0402_CC; HEIGHT: 0.45mm; MFG_NAME01: PANASONIC; MFG_PN01: ERJ2GEJ471X; ROHS: Yes; Tolerance: 5%
R207 R208 R512 = RES: RES MF 1.5K 1/16W 1% 0402; AGILE_PN: 470-80487; CAD_APPROVED: Yes; FPLIST: RC0402_25,RC0402_HD,0402_CC; HEIGHT: 0.4MM; MFG_NAME01: BOURNS; MFG_PN01: CR0402-FX-1501GLF; ROHS: Yes; Tolerance: 1%
TP201-TP208 TP402 TP403 = TESTLOOP: TEST POINT PAD 15MIL DIA SMT, NO PART TO ORDER; AGILE_PN: 211-76645; CAD_APPROVED: Yes; HEIGHT: 0.1MM; MFG_NAME01: NOTACOMPONENT; MFG_PN01: NOTACOMPONENT; ROHS: Yes
TP212 TP214 TP216 TP502-TP508 = T_POINT_R: TEST POINT PAD .035 SMT, no part to order; AGILE_PN: 510-75618; CAD_APPROVED: Yes; HEIGHT: 0.1MM; ROHS: Yes
U201 = MT41J256M16RE_FBGA96: IC MEM DDR3 SDRAM 256MX16 1.071NS 1.35V FBGA96; AGILE_PN: 334-77510; CAD_APPROVED: Yes; HEIGHT: 1.2 MM; MFG_NAME01: MICRON; ROHS: Yes; VOLTAGE: 1.35V
C407 C411 C412 = CAP_NP: CAP CER 1.0UF 10V 10% X5R 0402; AGILE_PN: 150-75772; CAD_APPROVED: Yes; FPLIST: CC0402_25,CC0402_HD,0402_CC; HEIGHT: 0.6MM; MFG_NAME01: YAGEO AMERICA; MFG_PN01: CC0402KRX5R6BB105; Package Size: 0402; ROHS: Yes; Rated Voltage: 10V; Temp Range: -55C to +85C; Tolerance: 10%; VOLTAGE: 10V
C414 = CAP_NP: CAP CER 820PF 50V 5% X7R 0402; AGILE_PN: 150-77973; ASSY_OPT: DNP; CAD_APPROVED: Yes; FPLIST: CC0402_25,CC0402_HD,0402_CC; HEIGHT: 0.6MM; MFG_NAME01: KEMET; MFG_PN01: C0402C821J5RAC; ROHS: Yes; Rated Voltage: 50V; Temp Range: -55C to +125C; Tolerance: 5%; VOLTAGE: 50 V
C415-C418 C505-C508 = CAP_NP: CAP CER 18PF 50V 1% C0G 0402; AGILE_PN: 150-76630; CAD_APPROVED: Yes; FPLIST: CC0402_25,CC0402_HD,0402_CC; HEIGHT: 0.59MM; MFG_NAME01: YAGEO; MFG_PN01: CC0402FRNPO9BN180; PRIORITY_PN: 021-00248; ROHS: Yes; ROOM: ATLAS-AP; Rated Voltage: 50V; Temp Range: -55C to +125C; Tolerance: 1%; VOLTAGE: 50V
C420-C423 = CAP_NP: CAP CER 18PF 50V 1% C0G 0402; AGILE_PN: 150-76630; ASSY_OPT: DNP; CAD_APPROVED: Yes; FPLIST: CC0402_25,CC0402_HD,0402_CC; HEIGHT: 0.59MM; MFG_NAME01: YAGEO; MFG_PN01: CC0402FRNPO9BN180; PRIORITY_PN: 021-00248; ROHS: Yes; ROOM: ATLAS-AP; Rated Voltage: 50V; Temp Range: -55C to +125C; Tolerance: 1%; VOLTAGE: 50V
R404 R412 R514 R516 R518 = RES: RES MF ZERO OHM 1/16W 5% 0402; AGILE_PN: 470-75394; CAD_APPROVED: Yes; FPLIST: RC0402_25,RC0402_HD,RC0402_X2,0402_CC; HEIGHT: 0.45 MM; MFG_NAME01: YAGEO AMERICA; MFG_PN01: RC0402JR-070RL; ROHS: Yes; Temp Range: -55 to +155C; Tolerance: 5%
R405 R501 R515 R517 = RES: RES MF ZERO OHM 1/16W 5% 0402; AGILE_PN: 470-75394; ASSY_OPT: DNP; CAD_APPROVED: Yes; FPLIST: RC0402_25,RC0402_HD,RC0402_X2,0402_CC; HEIGHT: 0.45 MM; MFG_NAME01: YAGEO AMERICA; MFG_PN01: RC0402JR-070RL; ROHS: Yes; Temp Range: -55 to +155C; Tolerance: 5%
R406-R411 R413 = RES: RES MF 10 OHM 1/16W 5% 0402; AGILE_PN: 470-75589; CAD_APPROVED: Yes; FPLIST: RC0402_25,RC0402_HD,0402_CC; HEIGHT: 0.4MM; MFG_NAME01: BOURNS; MFG_PN01: CR0402-JW-100GLF; ROHS: Yes; Tolerance: 5%
C503 = CAP_NP: CAP CER 0.1UF 25V 10% X5R 0402; AGILE_PN: 150-78633; ASSY_OPT: DNP; CAD_APPROVED: Yes; FPLIST: CC0402_25,CC0402_HD,0402_CC; HEIGHT: 0.55MM; MFG_NAME01: YAGEO AMERICA; MFG_PN01: CC0402KRX5R8BB104; Package Size: 0402; ROHS: Yes; Rated Voltage: 25V; Temp Range: -55C to +85C; Tolerance: 10%; VOLTAGE: 25V
Q501 = NMOSFET_3P_ESD_DIODE: TRAN NMOS SW 0.9V DRIVE 50V UMT3; AGILE_PN: 480-78966; ASSY_OPT: DNP; CAD_APPROVED: Yes; HEIGHT: 0.9MM; MFG_NAME01: ROHM; ROHS: Yes
R503 R507 = RES: RES MF 10K 1/16W 5% 0402; AGILE_PN: 470-75557; CAD_APPROVED: Yes; FPLIST: RC0402_25,RC0402_HD,0402_CC; HEIGHT: 0.4 MM; MFG_NAME01: BOURNS; MFG_PN01: CR0402-JW-103GLF; ROHS: Yes; TOL: 5%; Tolerance: 5%
R508 R513 = RES: RES MF 1M 1/10W 5% AEC-Q200 0402; AGILE_PN: 470-79978; ASSY_OPT: DNP; CAD_APPROVED: Yes; FPLIST: RC0402_25,RC0402_HD,0402_CC; HEIGHT: 0.4MM; MFG_NAME01: KOA SPEER; MFG_PN01: RK73B1ETTP105J; ROHS: Yes; Temp Range: -55&#8451; to 155&#8451;; Temp_Range: -55&#8451; to 155&#8451;; Tolerance: 5%
R510 = RES: RES MF 2.2M 1/10W 1% AEC-Q200 0402; AGILE_PN: 470-31210; CAD_APPROVED: Yes; FPLIST: RC0402_25,RC0402_HD,0402_CC; HEIGHT: 0.40 MM; MFG_NAME01: KOA SPEER; MFG_PN01: RK73H1ETTP2204F; ROHS: Yes; Temp Range: -55C to +155C; Temp_Range: -55C to +155C; Tolerance: 1%
R519 = RES: RES MF 100K 1/16W 5% 0402; AGILE_PN: 470-75597; ASSY_OPT: DNP; CAD_APPROVED: Yes; FPLIST: RC0402_25,RC0402_HD,0402_CC; HEIGHT: 0.40 MM; MFG_NAME01: SMEC; MFG_PN01: RC73L2Z104JTF; ROHS: Yes; Temp Range: -55C to +155C; Temp_Range: -55C to +155C; Tolerance: 5%
R520 = RES: RES MF 499 OHM 1/16W 1% 0402; AGILE_PN: 470-30807; ASSY_OPT: DNP; CAD_APPROVED: Yes; FPLIST: RC0402_25,RC0402_HD,0402_CC; HEIGHT: 0.40 MM; MFG_NAME01: ROHM; MFG_PN01: MCR01MZPF4990; ROHS: Yes; Tolerance: 1%
U501 = SGM803_SOT23-3P: IC VOLT MONITOR 2.63V RST VTH 1-5.5V AUTO SOT-23; AGILE_PN: 315-80553; CAD_APPROVED: Yes; HEIGHT: 1.25MM; MFG_NAME01: UNION SEMICONDUCTOR, INC; ROHS: Yes; VOLTAGE: 1-5.5V
Y501 = XTAL_13: XTAL 24MHZ 9pF -- SMT 3.2X2.5MM; AGILE_PN: 230-77392; CAD_APPROVED: Yes; HEIGHT: 0.60MM; MFG_NAME01: EPSON TOYOCOM CORPORATION; MFG_PN01: TSX-3225 24.0000MF15X-AC3; ROHS: Yes
Y502 = XTAL: XTAL 32.768KHZ 12.5pF -- SMT; 3D_Mechanical_Footprint_File: http://fcl.am.freescale.net/ALLEGRO/step/xtal2-3p2x1p5-sm.step; AGILE_PN: 230-77879; CAD_APPROVED: Yes; HEIGHT: 0.65MM; MFG_NAME01: MICRO CRYSTAL; MFG_PN01: CM7V-T1A, 32.768KHz, 12.5pF, 20ppm, TA, QC; ROHS: Yes
Y503 = SG8002: OSC 24MHZ FIXED 2.7-3.3V SMT; 3D_Mechanical_Footprint_File: http://fcl.am.freescale.net/ALLEGRO/step/xtlosc4_2p6x2p1mm_sm.STEP; AGILE_PN: 230-78110; ASSY_OPT: DNP; CAD_APPROVED: Yes; HEIGHT: 0.9MM; MFG_NAME01: NDK; MFG_PN01: ERG3199A; ROHS: Yes; VOLTAGE: 2.7-3.3V

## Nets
GND: C101.2 C102.2 C103.2 C106.2 C107.2 C108.2 C109.2 C111.2 C112.2 C113.2 C116.2 C117.2 C118.2 C119.2 C120.2 C121.2 C122.2 C123.2 C124.2 C201.2 C202.2 C203.2 C204.2 C205.2 C206.2 C207.2 C208.2 C209.2 C210.2 C211.2 C212.2 C213.2 C214.2 C215.2 C216.2 C217.2 C218.2 C219.2 C220.2 C221.2 C223.2 C224.2 C225.2 C226.2 C401.2 C402.2 C403.2 C404.2 C405.2 C407.2 C408.2 C409.2 C410.2 C411.2 C412.2 C413.2 C414.1 C415.1 C416.2 C417.1 C418.1 C420.1 C421.2 C422.1 C423.1 C501.2 C503.2 C505.2 C506.2 C507.2 C508.2 Q501.1(SOURCE) R201.1 R202.2 R203.2 R204.1 R205.1 R208.2 R209.2 R503.2 R507.2 R510.2 R516.2 R520.1 TP212.1(TP) TP214.1(TP) TP216.1(TP) U101.A1(VSS1) U101.A17(VSS2) U101.C3(VSS3) U101.C7(VSS4) U101.C11(VSS5) U101.C15(VSS6) U101.E8(VSS7) U101.E11(VSS8) U101.F6(VSS9) U101.F7(VSS10) U101.F8(VSS11) U101.F9(VSS12) U101.F10(VSS13) U101.F11(VSS14) U101.F12(VSS15) U101.G3(VSS16) U101.G5(VSS17) U101.G7(VSS18) U101.G12(VSS19) U101.G15(VSS20) U101.H7(VSS21) U101.H12(VSS22) U101.J5(VSS23) U101.J7(VSS24) U101.J12(VSS25) U101.K7(VSS26) U101.K12(VSS27) U101.L3(VSS28) U101.L7(VSS29) U101.L12(VSS30) U101.M7(VSS31) U101.M8(VSS32) U101.M9(VSS33) U101.M10(VSS34) U101.M11(VSS35) U101.M12(NGND_KEL0) U101.N3(VSS36) U101.N5(VSS37) U101.N7(TEST_MODE) U101.R3(VSS38) U101.R5(VSS39) U101.R7(VSS40) U101.R11(VSS41) U101.R16(VSS42) U101.R17(VSS43) U101.T14(VSS44) U101.U1(VSS45) U101.U14(VSS46) U101.U17(VSS47) U201.A9(VSS1) U201.B1(VSSQ1) U201.B3(VSS2) U201.B9(VSSQ2) U201.D1(VSSQ3) U201.D8(VSSQ4) U201.E1(VSS3) U201.E2(VSSQ5) U201.E8(VSSQ6) U201.F9(VSSQ7) U201.G1(VSSQ8) U201.G8(VSS4) U201.G9(VSSQ9) U201.J2(VSS5) U201.J8(VSS6) U201.M1(VSS7) U201.M9(VSS8) U201.P1(VSS9) U201.P9(VSS10) U201.T1(VSS11) U201.T9(VSS12) U501.1(GND) Y501.4 Y503.2(GND) ; also on sheet 8 9 10 13
VDD_ARM_CAP: C102.1 C103.1 C106.1 U101.G9(VDD_ARM_CAP1) U101.G10(VDD_ARM_CAP2) U101.G11(VDD_ARM_CAP3) U101.H11(VDD_ARM_CAP4)
VDD_ARM_SOC_IN: C101.1 C107.1 C108.1 C109.1 U101.H9(VDD_SOC_IN1) U101.H10(VDD_SOC_IN2) U101.J9(VDD_SOC_IN3) U101.J10(VDD_SOC_IN4) U101.K9(VDD_SOC_IN5) U101.K10(VDD_SOC_IN6) ; also on sheet 9
VDD_COIN_3V: D103.A R101.1 ; also on sheet 10
VDD_HIGH_CAP: C119.1 C120.1 C201.1 U101.N6(NVCC_DRAM_2P5) U101.R14(VDD_HIGH_CAP1) U101.R15(VDD_HIGH_CAP2)
VDD_HIGH_IN: C117.1 C118.1 U101.N13(VDD_HIGH_IN) ; also on sheet 9
VDD_SNVS_3V3: D102.A ; also on sheet 9
VDD_SNVS_CAP: C124.1 U101.N12(VDD_SNVS_CAP)
VDD_SNVS_IN: C123.1 D102.C D103.C R101.2 R519.1 U101.P12(VDD_SNVS_IN) ; also on sheet 8 10
VDD_SOC_CAP: C111.1 C112.1 C113.1 C116.1 U101.G8(VDD_SOC_CAP1) U101.H8(VDD_SOC_CAP2) U101.J8(VDD_SOC_CAP3) U101.J11(VDD_SOC_CAP4) U101.K8(VDD_SOC_CAP5) U101.K11(VDD_SOC_CAP6) U101.L8(VDD_SOC_CAP7) U101.L9(VDD_SOC_CAP8) U101.L10(VDD_SOC_CAP9) U101.L11(VDD_SOC_CAP10)
VDDA_ADC_3P3: C410.1 C411.1 U101.L13(VDDA_ADC_3P3) U101.M13(ADC_VREFH) ; also on sheet 9
VDDUSB: C408.1 C409.1 U101.R12(VDD_USB_CAP)
ACC_INT: U101.R10(SNVS_TAMPER0) ; also on sheet 10
AUD_INT: U101.P9(SNVS_TAMPER4) ; also on sheet 10
BLT_PWM: U101.N17(GPIO1_IO08) ; also on sheet 10
BOOT_MODE0: U101.T10(BOOT_MODE0) ; also on sheet 8 10
BOOT_MODE1: U101.U10(BOOT_MODE1) ; also on sheet 8 10
BT_DISABLE: U101.R9(SNVS_TAMPER1) ; also on sheet 10
CAN1_RX: U101.G14(~{UART3_RTS}) ; also on sheet 10
CAN1_TX: U101.H15(~{UART3_CTS}) ; also on sheet 10
CAN2_RX: U101.H14(~{UART2_RTS}) ; also on sheet 10
CAN2_TX: U101.J15(~{UART2_CTS}) ; also on sheet 10
CLK1_N: U101.P16(CCM_CLK1_N) ; also on sheet 10
CLK1_P: U101.P17(CCM_CLK1_P) ; also on sheet 10
CSI_DATA0: U101.E4(CSI_DATA00) ; also on sheet 10
CSI_DATA1: U101.E3(CSI_DATA01) ; also on sheet 10
CSI_DATA2: U101.E2(CSI_DATA02) ; also on sheet 10
CSI_DATA3: U101.E1(CSI_DATA03) ; also on sheet 10
CSI_DATA4: U101.D4(CSI_DATA04) ; also on sheet 10
CSI_DATA5: U101.D3(CSI_DATA05) ; also on sheet 10
CSI_DATA6: U101.D2(CSI_DATA06) ; also on sheet 10
CSI_DATA7: U101.D1(CSI_DATA07) ; also on sheet 10
CSI_HSYNC: U101.F3(CSI_HSYNC) ; also on sheet 10
CSI_MCLK: U101.F5(CSI_MCLK) ; also on sheet 10 13
CSI_PIXCLK: U101.E5(CSI_PIXCLK) ; also on sheet 10 13
CSI_VSYNC: U101.F2(CSI_VSYNC) ; also on sheet 10
DCDC_3V3: C401.1 C402.1 C413.1 R512.1 R513.1 R517.2 U101.E13(NVCC_LCD) U101.F13(NVCC_ENET) U101.H13(NVCC_UART) U101.J13(NVCC_GPIO) ; also on sheet 8 9 10 13
DRAM_1V35: C205.1 C206.1 C207.1 C208.1 C209.1 C210.1 C211.1 C212.1 C213.1 C214.1 C215.1 C216.1 C217.1 C218.1 C219.1 C220.1 C221.1 C222.1 C223.1 C225.1 C226.1 R207.1 U101.G6(NVCC_DRAM1) U101.H6(NVCC_DRAM2) U101.J6(NVCC_DRAM3) U101.K6(NVCC_DRAM4) U101.L6(NVCC_DRAM5) U101.M6(NVCC_DRAM6) U201.A1(VDDQ1) U201.A8(VDDQ2) U201.B2(VDD1) U201.C1(VDDQ3) U201.C9(VDDQ4) U201.D2(VDDQ5) U201.D9(VDD2) U201.E9(VDDQ6) U201.F1(VDDQ7) U201.G7(VDD3) U201.H2(VDDQ8) U201.H9(VDDQ9) U201.K2(VDD4) U201.K8(VDD5) U201.N1(VDD6) U201.N9(VDD7) U201.R1(VDD8) U201.R9(VDD9) ; also on sheet 9
DRAM_ADDR0: TP207.1(Pin1) TP208.1(Pin1) U101.L5(DRAM_ADDR00) U201.N3(A0)
DRAM_ADDR1: U101.H2(DRAM_ADDR01) U201.P7(A1)
DRAM_ADDR2: U101.K1(DRAM_ADDR02) U201.P3(A2)
DRAM_ADDR3: U101.M2(DRAM_ADDR03) U201.N2(A3)
DRAM_ADDR4: U101.K4(DRAM_ADDR04) U201.P8(A4)
DRAM_ADDR5: U101.L1(DRAM_ADDR05) U201.P2(A5)
DRAM_ADDR6: U101.G2(DRAM_ADDR06) U201.R8(A6)
DRAM_ADDR7: U101.H4(DRAM_ADDR07) U201.R2(A7)
DRAM_ADDR8: U101.J4(DRAM_ADDR08) U201.T8(A8)
DRAM_ADDR9: U101.L2(DRAM_ADDR09) U201.R3(A9)
DRAM_ADDR10: U101.M4(DRAM_ADDR10) U201.L7(A10/AP)
DRAM_ADDR11: U101.K3(DRAM_ADDR11) U201.R7(A11)
DRAM_ADDR12: U101.L4(DRAM_ADDR12) U201.N7(A12/~{BC})
DRAM_ADDR13: U101.H3(DRAM_ADDR13) U201.T3(A13)
DRAM_ADDR14: U101.G1(DRAM_ADDR14) U201.T7(A14)
DRAM_ADDR15: U101.K5(DRAM_ADDR15) U201.M7(NC)
DRAM_CAS_B: U101.J2(~{DRAM_CAS}) U201.K3(~{CAS})
DRAM_CS0_B: U101.N2(~{DRAM_CS0}) U201.L2(~{CS})
DRAM_CS1_B: U101.H5(~{DRAM_CS1}) U201.L1(NC)
DRAM_DATA0: TP202.1(Pin1) TP204.1(Pin1) U101.T4(DRAM_DATA00) U201.E3(DQ0)
DRAM_DATA1: U101.U6(DRAM_DATA01) U201.H3(DQ4)
DRAM_DATA2: U101.T6(DRAM_DATA02) U201.H7(DQ7)
DRAM_DATA3: U101.U7(DRAM_DATA03) U201.F8(DQ3)
DRAM_DATA4: U101.U8(DRAM_DATA04) U201.F7(DQ1)
DRAM_DATA5: U101.T8(DRAM_DATA05) U201.H8(DQ5)
DRAM_DATA6: U101.T5(DRAM_DATA06) U201.G2(DQ6)
DRAM_DATA7: U101.U4(DRAM_DATA07) U201.F2(DQ2)
DRAM_DATA8: U101.U2(DRAM_DATA08) U201.D7(DQ8)
DRAM_DATA9: U101.U3(DRAM_DATA09) U201.C3(DQ9)
DRAM_DATA10: U101.U5(DRAM_DATA10) U201.C8(DQ10)
DRAM_DATA11: U101.R4(DRAM_DATA11) U201.C2(DQ11)
DRAM_DATA12: U101.P5(DRAM_DATA12) U201.A7(DQ12)
DRAM_DATA13: U101.P3(DRAM_DATA13) U201.A2(DQ13)
DRAM_DATA14: U101.R2(DRAM_DATA14) U201.B8(DQ14)
DRAM_DATA15: U101.R1(DRAM_DATA15) U201.A3(DQ15)
DRAM_DQM0: U101.T7(DRAM_DQM0) U201.E7(LDM)
DRAM_DQM1: U101.T3(DRAM_DQM1) U201.D3(UDM)
DRAM_ODT0: U101.N1(DRAM_ODT0) U201.K1(ODT)
DRAM_ODT1: U101.F1(DRAM_ODT1) U201.J1(NC)
DRAM_RAS_B: U101.M5(~{DRAM_RAS}) U201.J3(~{RAS})
DRAM_RESET_B: R201.2 U101.G4(DRAM_RESET) U201.T2(~{RESET})
DRAM_SDBA0: U101.M1(DRAM_SDBA0) U201.M2(BA0)
DRAM_SDBA1: U101.H1(DRAM_SDBA1) U201.N8(BA1)
DRAM_SDBA2: U101.K2(DRAM_SDBA2) U201.M3(BA2)
DRAM_SDCKE0: R203.1 U101.M3(DRAM_SDCKE0) U201.K9(CKE)
DRAM_SDCKE1: R202.1 U101.J3(DRAM_SDCKE1) U201.J9(NC)
DRAM_SDCLK0_N: R206.2 TP205.1(Pin1) TP206.1(Pin1) U101.P2(DRAM_SDCLK0_N) U201.K7(~{CK})
DRAM_SDCLK0_P: R206.1 TP201.1(Pin1) TP203.1(Pin1) U101.P1(DRAM_SDCLK0_P) U201.J7(CK)
DRAM_SDQS0_N: C227.2 C229.2 U101.P7(DRAM_SDQS0_N) U201.G3(~{LDQS})
DRAM_SDQS0_P: C227.1 C229.1 U101.P6(DRAM_SDQS0_P) U201.F3(LDQS)
DRAM_SDQS1_N: C228.2 C230.2 U101.T2(DRAM_SDQS1_N) U201.B7(~{UDQS})
DRAM_SDQS1_P: C228.1 C230.1 U101.T1(DRAM_SDQS1_P) U201.C7(UDQS)
DRAM_SDWE_B: U101.J1(~{DRAM_SDWE}) U201.L3(~{WE})
DRAM_VREF: C202.1 C203.1 C204.1 C222.2 C224.1 R207.2 R208.1 U101.P4(DRAM_VREF) U201.H1(VREFDQ) U201.M8(VREFCA)
DRAM_ZQ0: R204.2 U201.L8(ZQ)
DRAM_ZQ1: R209.1 U201.L9(NC)
ECSPI4_MISO: C416.1 R410.2 ; also on sheet 10
ECSPI4_MOSI: U101.B15(ENET2_TX_EN) ; also on sheet 10
ECSPI4_SCLK: U101.A16(ENET2_TX_DATA1) ; also on sheet 10
ECSPI4_SS0: U101.D16(ENET2_RX_ER) ; also on sheet 10
ENET1_CRS_DV: U101.E16(ENET1_RX_EN) ; also on sheet 10
ENET1_nINT: U101.N8(SNVS_TAMPER5) ; also on sheet 10
ENET1_RXD0: TP402.1(Pin1) U101.F16(ENET1_RX_DATA0) ; also on sheet 10
ENET1_RXD1: U101.E17(ENET1_RX_DATA1) ; also on sheet 10
ENET1_RXER: U101.D15(ENET1_RX_ER) ; also on sheet 10
ENET1_TX_CLK: C417.2 R409.2 ; also on sheet 10
ENET1_TXD0: U101.E15(ENET1_TX_DATA0) ; also on sheet 10
ENET1_TXD1: U101.E14(ENET1_TX_DATA1) ; also on sheet 10
ENET1_TXEN: U101.F15(ENET1_TX_EN) ; also on sheet 10
ENET2_CRS_DV: U101.B17(ENET2_RX_EN) ; also on sheet 10
ENET2_nINT: U101.N11(SNVS_TAMPER6) ; also on sheet 10
ENET2_RXD0: TP403.1(Pin1) U101.C17(ENET2_RX_DATA0) ; also on sheet 10
ENET2_RXD1: U101.C16(ENET2_RX_DATA1) ; also on sheet 10
ENET2_TXD0: U101.A15(ENET2_TX_DATA0) ; also on sheet 10
ENET_MDC: U101.L16(GPIO1_IO07) ; also on sheet 10
ENET_MDIO: U101.K17(GPIO1_IO06) ; also on sheet 10
GPANAIO: U101.R13(GPANAIO)
GPIO_0: U101.K13(GPIO1_IO00) ; also on sheet 10
GPIO_1: U101.L15(GPIO1_IO01) ; also on sheet 10
GPIO_2: U101.L14(GPIO1_IO02) ; also on sheet 10
GPIO_3: U101.L17(GPIO1_IO03) ; also on sheet 10
GPIO_4: U101.M16(GPIO1_IO04) ; also on sheet 10
GPIO_5: U101.M17(GPIO1_IO05) ; also on sheet 9 10
GPIO_9: U101.M15(GPIO1_IO09) ; also on sheet 10
GPIO_DVFS: U101.P10(SNVS_TAMPER3) ; also on sheet 9 10
HDMI_INT: U101.K15(~{UART1_CTS}) ; also on sheet 10
I2C1_SCL: U101.G17(UART4_TX_DATA) ; also on sheet 10
I2C1_SDA: U101.G16(UART4_RX_DATA) ; also on sheet 10
I2C2_SCL: U101.F17(UART5_TX_DATA) ; also on sheet 10
I2C2_SDA: U101.G13(UART5_RX_DATA) ; also on sheet 10
JTAG_MOD: R507.1 U101.P15(JTAG_MOD) ; also on sheet 10
JTAG_nTRST: TP502.1(TP) U101.N14(~{JTAG_TRST}) ; also on sheet 10
JTAG_TCK: R503.1 TP505.1(TP) U101.M14(JTAG_TCK) ; also on sheet 10
JTAG_TDI: TP503.1(TP) U101.N16(JTAG_TDI) ; also on sheet 10
JTAG_TDO: TP506.1(TP) U101.N15(JTAG_TDO) ; also on sheet 10
JTAG_TMS: TP504.1(TP) U101.P14(JTAG_TMS) ; also on sheet 10
LCD_DATA0: U101.B9(LCD_DATA00) ; also on sheet 8 10
LCD_DATA1: U101.A9(LCD_DATA01) ; also on sheet 8 10
LCD_DATA2: U101.E10(LCD_DATA02) ; also on sheet 8 10
LCD_DATA3: U101.D10(LCD_DATA03) ; also on sheet 8 10
LCD_DATA4: U101.C10(LCD_DATA04) ; also on sheet 8 10
LCD_DATA5: U101.B10(LCD_DATA05) ; also on sheet 8 10
LCD_DATA6: U101.A10(LCD_DATA06) ; also on sheet 8 10
LCD_DATA7: U101.D11(LCD_DATA07) ; also on sheet 8 10
LCD_DATA8: U101.B11(LCD_DATA08) ; also on sheet 8 10
LCD_DATA9: U101.A11(LCD_DATA09) ; also on sheet 8 10
LCD_DATA10: U101.E12(LCD_DATA10) ; also on sheet 8 10
LCD_DATA11: U101.D12(LCD_DATA11) ; also on sheet 8 10
LCD_DATA12: U101.C12(LCD_DATA12) ; also on sheet 8 10
LCD_DATA13: U101.B12(LCD_DATA13) ; also on sheet 8 10
LCD_DATA14: U101.A12(LCD_DATA14) ; also on sheet 8 10
LCD_DATA15: U101.D13(LCD_DATA15) ; also on sheet 8 10
LCD_DATA16: U101.C13(LCD_DATA16) ; also on sheet 8 10
LCD_DATA17: U101.B13(LCD_DATA17) ; also on sheet 8 10
LCD_DATA18: U101.A13(LCD_DATA18) ; also on sheet 8 10
LCD_DATA19: U101.D14(LCD_DATA19) ; also on sheet 8 10
LCD_DATA20: U101.C14(LCD_DATA20) ; also on sheet 8 10
LCD_DATA21: U101.B14(LCD_DATA21) ; also on sheet 8 10
LCD_DATA22: U101.A14(LCD_DATA22) ; also on sheet 8 10
LCD_DATA23: U101.B16(LCD_DATA23) ; also on sheet 8 10
LCD_DE: U101.B8(LCD_ENABLE) ; also on sheet 10
LCD_DISP: U101.R6(SNVS_TAMPER9) ; also on sheet 10
LCD_HSYNC: U101.D9(LCD_HSYNC) ; also on sheet 10
LCD_PCLK: C414.2 R413.2 ; also on sheet 10
LCD_RESET: R404.1 R405.1 U101.E9(LCD_RESET)
LCD_RST: R405.2 ; also on sheet 10
LCD_VSYNC: U101.C9(LCD_VSYNC) ; also on sheet 10
NAND_ALE: R412.2 ; also on sheet 13
NAND_CLE: U101.A4(NAND_CLE) ; also on sheet 13
NAND_DATA0: U101.D7(NAND_DATA00) ; also on sheet 13
NAND_DATA1: U101.B7(NAND_DATA01) ; also on sheet 13
NAND_DATA2: U101.A7(NAND_DATA02) ; also on sheet 13
NAND_DATA3: U101.D6(NAND_DATA03) ; also on sheet 13
NAND_DATA4: U101.C6(NAND_DATA04) ; also on sheet 13
NAND_DATA5: U101.B6(NAND_DATA05) ; also on sheet 13
NAND_DATA6: U101.A6(NAND_DATA06) ; also on sheet 13
NAND_DATA7: U101.A5(NAND_DATA07) ; also on sheet 13
NAND_DQS: R408.2 ; also on sheet 13
NAND_nCE0: U101.C5(~{NAND_CE0}) ; also on sheet 13
NAND_nCE1: U101.B5(~{NAND_CE1}) ; also on sheet 13
NAND_nRE: C415.2 R406.2 ; also on sheet 13
NAND_nREADY: U101.A3(~{NAND_READY}) ; also on sheet 13
NAND_nWE: R407.2 ; also on sheet 13
NAND_nWP: U101.D5(~{NAND_WP}) ; also on sheet 13
nUSB_OTG_CHD: U101.U16(~{USB_OTG1_CHD}) ; also on sheet 10
NVCC_CSI: C404.1 U101.F4(NVCC_CSI) ; also on sheet 9 10
NVCC_NAND: C403.1 U101.E7(NVCC_NAND) ; also on sheet 9 13
NVCC_PLL_OUT: C121.1 C122.1 U101.P13(NVCC_PLL)
NVCC_SD: C405.1 R402.1 R403.1 U101.C4(NVCC_SD1) ; also on sheet 9
nWDOG: R404.2 ; also on sheet 9
ONOFF: TP508.1(TP) U101.R8(ONOFF) ; also on sheet 10
OSC_CLK: C506.1 R508.2 R514.1 Y501.1 Y503.3(OUT)
PERI_PWREN: U101.P11(SNVS_TAMPER2) ; also on sheet 10
PMIC_ON_REQ: U101.T9(SNVS_PMIC_ON_REQ) ; also on sheet 9 10
PMIC_STBY_REQ: Q501.2(GATE) U101.U9(CCM_PMIC_STBY_REQ) ; also on sheet 9 10
POR_B: C503.1 R511.2 R519.2 TP507.1(TP) U101.P8(~{POR}) ; also on sheet 10
RTC_XTALI: C507.1 U101.T11(RTC_XTALI) Y502.1
RTC_XTALO: C508.1 U101.U11(RTC_XTALO) Y502.2
SD1_CD: U101.J14(~{UART1_RTS}) ; also on sheet 10
SD1_CLK: C418.2 R411.2 ; also on sheet 10
SD1_CMD: R402.2 U101.C2(SD1_CMD) ; also on sheet 10
SD1_DATA0: R403.2 U101.B3(SD1_DATA0) ; also on sheet 10
SD1_DATA1: U101.B2(SD1_DATA1) ; also on sheet 10
SD1_DATA2: U101.B1(SD1_DATA2) ; also on sheet 10
SD1_DATA3: U101.A2(SD1_DATA3) ; also on sheet 10
SHIFT_nOE: U101.N9(SNVS_TAMPER8) ; also on sheet 10
SHIFT_STCP: U101.N10(SNVS_TAMPER7) ; also on sheet 10
UART1_RXD: U101.K16(UART1_RX_DATA) ; also on sheet 10
UART1_TXD: U101.K14(UART1_TX_DATA) ; also on sheet 10
UART2_CTS_BB: U101.H17(UART3_TX_DATA) ; also on sheet 10
UART2_RTS_BB: U101.H16(UART3_RX_DATA) ; also on sheet 10
UART2_RXD: U101.J16(UART2_RX_DATA) ; also on sheet 10
UART2_TXD: U101.J17(UART2_TX_DATA) ; also on sheet 10
USB_OTG1_DN: U101.T15(USB_OTG1_DN) ; also on sheet 10
USB_OTG1_DP: U101.U15(USB_OTG1_DP) ; also on sheet 10
USB_OTG1_VBUS: C407.1 U101.T12(USB_OTG1_VBUS) ; also on sheet 10
USB_OTG2_DN: U101.T13(USB_OTG2_DN) ; also on sheet 10
USB_OTG2_DP: U101.U13(USB_OTG2_DP) ; also on sheet 10
USB_OTG2_VBUS: C412.1 U101.U12(USB_OTG2_VBUS) ; also on sheet 10
XTAL_CMPT: R516.1 R517.1 Y501.2 Y503.4(VCC)
XTALI: C505.1 R508.1 R510.1 R518.1 U101.T16(XTALI)
XTALO: R514.2 R520.2 U101.T17(XTALO)
ZQPAD: R205.2 U101.N4(DRAM_ZQPAD)
N299288: R413.1 U101.A8(LCD_CLK)
N300247: C420.2 R409.1 U101.F14(ENET1_TX_CLK)
N300263: C421.1 R410.1 U101.D17(ENET2_TX_CLK)
N309462: R515.2 R518.2 Y501.3 Y503.1(~{ST})
N98008264: C422.2 R411.1 U101.C1(SD1_CLK)
N98645062: C501.1 R501.1 R512.2 U501.3(VCC)
N98645064: R501.2 R511.1 U501.2(~{RESET})
N99172123: Q501.3(DRAIN) R513.2 R515.1
N100072724: C423.2 R406.1 U101.D8(~{NAND_RE})
N100072774: R412.1 U101.B4(NAND_ALE)
N100072844: R407.1 U101.C8(~{NAND_WE})
N100072898: R408.1 U101.E6(NAND_DQS)

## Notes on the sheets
sheet 1
- LDO
- VDD_SNVS_IN
- Always ON
- RICHTEK RT9169
- VDD_SNVS_IN
- LDO_ARM_SOC
- VDD_SNVS_CAP
- 3.3V/100mA Iq = 4uA
- 276uA
- LDO_1P1
- NVCC_PLL
- WALL Adapter: 5V/3A
- OVP
- DC/DC BUCK
- VDD_HIGH_IN
- VSYS
- VDD_HIGH_IN
- LDO_2P5
- VDD_HIGH_CAP
- PMIC_ON_REQ
- MPS MP2144
- 5V/3A
- 3.3V/2A Iq=40uA
- DCDC_3V3
- 125mA
- NVCC_GPIO/NVCC_ENET/NVCC_LCDIF
- NVCC_DRAM_2P5
- # MCIMX6ULL-BB
- DC/DC BUCK
- VDDARM_IN
- VDD_ARM_CAP
- VDD_SOC_IN
- LDO_ARM_SOC
- DCDC_3V3_PG
- AP3401KT
- 900mA
- VDD_SOC_CAP
- 1.275V/1A Iq=40uA
- DC/DC BUCK
- VDD_MEM1V5
- NVCC_DRAM
- AP3401KT
- DCDC_3V3_PG
- 50mA
- i.MX6ULL
- 1.35V/1A Iq=40uA
- NVCC_NAND
- # 1.8V for eMMC HS200 mode
- LDO
- RICHTEK RT9169
- 1.8V/100mA Iq = 4uA
- HIGH PSRR LDO
- VLDO_3V3
- RICHTEK RT9193
- VDDA_ADC_3P3
- DCDC_3V3_PG
- 3.3V/300mA
- LDO
- NVCC_SD (3.3V/1.8V)
- UM1750S-00
- NVCC_SD
- DCDC_3V3_PG
- 1.8V/3.3V/500mA
- # 1.8V for CSI;
  1.8V/3.3V for SIM
- NVCC_CSI (1.8V/3.3V)
- NVCC_CSI
- USB_OTG_VBUS
- 50mA
- USB_OTG1_VBUS
- LOAD SW
- USB_HOST_VBUS
- LDO_USB
- VDD_USB_CAP
- USB_OTGx_PWR
- USB_OTG2_VBUS
- VLCD_3V3
- 3.3V/23mA
- FPC Connector
- BLT_PWM
- LvDDR3
- Micron: MT41K512M16
  or MT41K256M16
- VHDMI_3V3
- HDMI
- 3.3V/10mA
- DCDC_3V3
- LDO
- SILICON IMAGE SiI9022A
- VLDO_1V2
- 3.3V/200mA
- eMMC 4GB
- 1.2V/69.2mA
- RICHTEK RT9169
- Micron
  MTFC8GACAAAM
- VSPK_5V
- NVCC_NAND
- 5V/511mA
- 3.3V/1.8V
- Audio Codec
- DVDD_1V8
- LDO
- Wolfson WM8962B
- VAUD_3V3
- UM1750S-00
- DCDC_3V3
- QSPI
- 3.3V/62.58mA
- 3.3V/20mA
- Micron MT25QL256
- SENSOR
- VSENSOR_3V3
- eCompass/
  G-sensor/Gyroscope
- 3.3V/6.9mA
- DCDC_3V3
- NAND
- # MCIMX6ULL-CM
- 3.3V/50mA
- Micron MT29F32G08
- CAN_VIO_3V3
- CAN
- 3.3V/1mA
- NXP  TJA1044GT/3
- CAN_VDD_5V
- 5V/65mA
- USB_OTG_VBUS
- USB OTG
- Ethernet x2
- VENET_3V3
- 3.3V/48.7mA
- LOAD SW
- USB_HOST_VBUS
- Micrel KSZ8081RNB
- USB HOST
- AVDD_2V8
- LDO
- UM1750S-00
- SD Socket
- 2.8V/500mA
- LOAD SW
- SD1_nRST/POR_B
- Camera/EMV SIM
- CSI B2B CN
- LDO
- DVDD1V5
- BT MOD
- UM1750S-00
- 1.5V/500mA
sheet 2
- i.MX6ULL EVK Block Diagram
- MPN: MCIMX6ULL-BB
  MPN: MCIMX6ULL-CM
- Agile No: 28616
  Agile No: 29364
- EMV SIM Socket
- smart card
- HDMI
- FPC
- Camera
- CAN x2
- JTAG
- Micro USB
- USB HOST
- Connector
- Silicon Image
     SiI9022A
- OV5642 5MP
- NXP TJA1044GT/3
- PIN Header
- DISP
- CSI/SIM
- USB OTG1
- USB OTG2
- CAN x2
- JTAG
- SODIMM
- NAND
- PWR
- eMMC/MicroSD
- POWER
- eMMC 4.51 Footprint only
- Discrete PWR
- NAND/SDIO/QSPI
- NAND/SD2/QSPIA
- QSPI
- Micron MT25QL256
- i.MX6ULL
- DDR3/LvDDR3
- x16 bits
- DRAM
- Micron 8Gb: MT41K512M16
  or 4Gb: MT41K256M16
- SODIMM
- UART
- I2C/INT
- SD1
- RMII x2
- I2S
- UART
- Motion  Sensors
- BlueTooth
- SD SLOT
- Ethernet x2 (RMII)
- CODEC
- UART-USB bridge
- eCompass MAG3110FCR2
- Full Size
- Silabs CP2102
- FPC Module
- Accelerometer FXLS8974CFR3
- 100Base-T Micrel KSZ8081
- Wolfson WM8962B
- Gyroscope: FXAS21002CQ
- HP
- MIC
sheet 3
- MCIMX6ULL-CM
- Schematics DevBoard
- Table of Content
- Revision History
- Page 1
- Cover
- Rev. Code
- Date
- By
- Description
- Page 2
- Block Diagram
- A
- 2016-07-22
- Yizhou
- Compare to i.MX 6UL EVK C3
- 1
- Change U101 CPU part number to MCIMX6Y2DVM05AA
- Page 3
- PWR TREE
- 2
- Change DDR part number to MT41K256M16TW-107:P
- 3
- Change QSPI flash part number to MT25QL256ABA1EW9
- Page 4
- CPU PWR
- 4
- Remove EVMSIM
- Page 5
- LvDDR3
- A1
- 25-May-2018
- Marek B.
- U101 updated to MCIMX6Y2DVM09AB
- Page 6
- eMMC/NAND/TF/QSPI
- B
- 15-Sept-2022
- Annanya
  Gupta
- 1. J301 is updated to 472192001 Molex
  2. Y501 is updated to TSX-3225 24.0000MF15X-AC3
  3. U702, U706 is updated to AP3401KTTR-G1
  4. SW602 is updated to 1571983-1
  5. D701,702,705 is updated to RB521S30T1G
- Page 7
- CPU PERI1
- Page 8
- CPU PERI2
- Page 9
- BOOT CFG
- Page 10
- PWR MGR
- B1
- 13-Oct-2023
- Silong Ren
- Update the Block Diagram
- Page 11
- SO-DIMM
- Page 12
- NOTE
- Page 13
- IOMUX
- Page 14
- Page 15
- Page 16
- Page 17
- Page 18
- Page 19
- Page 20
- Page 21
- Page 22
- Page 23
- Page 24
- Page 25
- Page 26
- Page 26
- Page 27
- Page 28
- 3. Device type number is for reference only. The number
      varies with the manufacturer.
- 1. Unless Otherwise Specified:
- All resistors are in ohms, 10%, 1/8 Watt,0603
- 4. Special signal usage:
- All capacitors are in uF, 20%, 50V,0603
- _B Denotes - Active-Low Signal
- All voltages are DC
- <> or [] Denotes - Vectored Signals
- All polarized capacitors are aluminum electrolytic
- 5. Interpret diagram in accordance with American
  National Standards Institute specifications, current
  revision, with the exception of logic block symbology.
- 2. Interrupted lines coded with the same letter or letter
      combinations are electrically connected.
sheet 4
- i.MX6ULL PWR
- # Confirm the coin cell discharge curr >40uA if used
sheet 5
- DDR3/LvDDR3
- J1/J9/L1/L9 Reserved for Use with
  Twin-Die DDR3L
  Micron P/N: MT41K512M16TNA
- 8Gb: MT41K512M16HA-125 IT
  4Gb: MT41K256M16TW-107:P
- Add 10uF
- Note:
  CLK termination: Place R206 close to U2.
- DDR3 VREF
- DRAM Test Points
- # Note: 1K/1.5K are OK
- # Note:
  Test points for signal integrity measurement
sheet 6
- MX6ULL PERI
- # QSPI_DQS only for loop back mode test
- # LCD RGB
- # NAND/eMMC/MicroSD/QSPI
- # Camera
- # Layout: Route 90ohm DIFF
- # Layout: Route 90ohm DIFF
- # SD CARD FULL SIZE
- # 100M MII/RMII
- # Ethernet / SPI
sheet 7
- JTAG Debug
- i.MX6ULL RESET
- # Open Drain
- PU (100K)
- PU (100K)
- PU (47K)
- PD (100K)
- PD (100K)
- PU (47K)
- PU (47K)
- PD (100K)
- PU (100K)
- PU (47K)
- PU (100K)
- # NVCC_GPIO (J13) and NVCC_UART (H13)
  should share one 0.22uF de-coupling cap.
  There is no PCB space to fit two caps.
- # DBG
- PD (100K)
- PU (100K)
- # BT
- If oscillator used:
  R514:300 OHM; R520: 150 OHM;
- Y503 used 3225 PCB footprint
  ("xtlosc4_3p2x2p5mm_sm")
  to be compatible with 2520 package oscillator.
